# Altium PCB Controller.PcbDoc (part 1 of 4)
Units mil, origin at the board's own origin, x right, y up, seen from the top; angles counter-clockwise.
Board outline 5000 x 8750 mil, 6 copper layers (Top Layer, Layer 1, Layer 2, Layer 3, Layer 4, Bottom Layer), stack 92.6 mil thick; 303 components, 258 nets, 1062 pads, 274 vias.
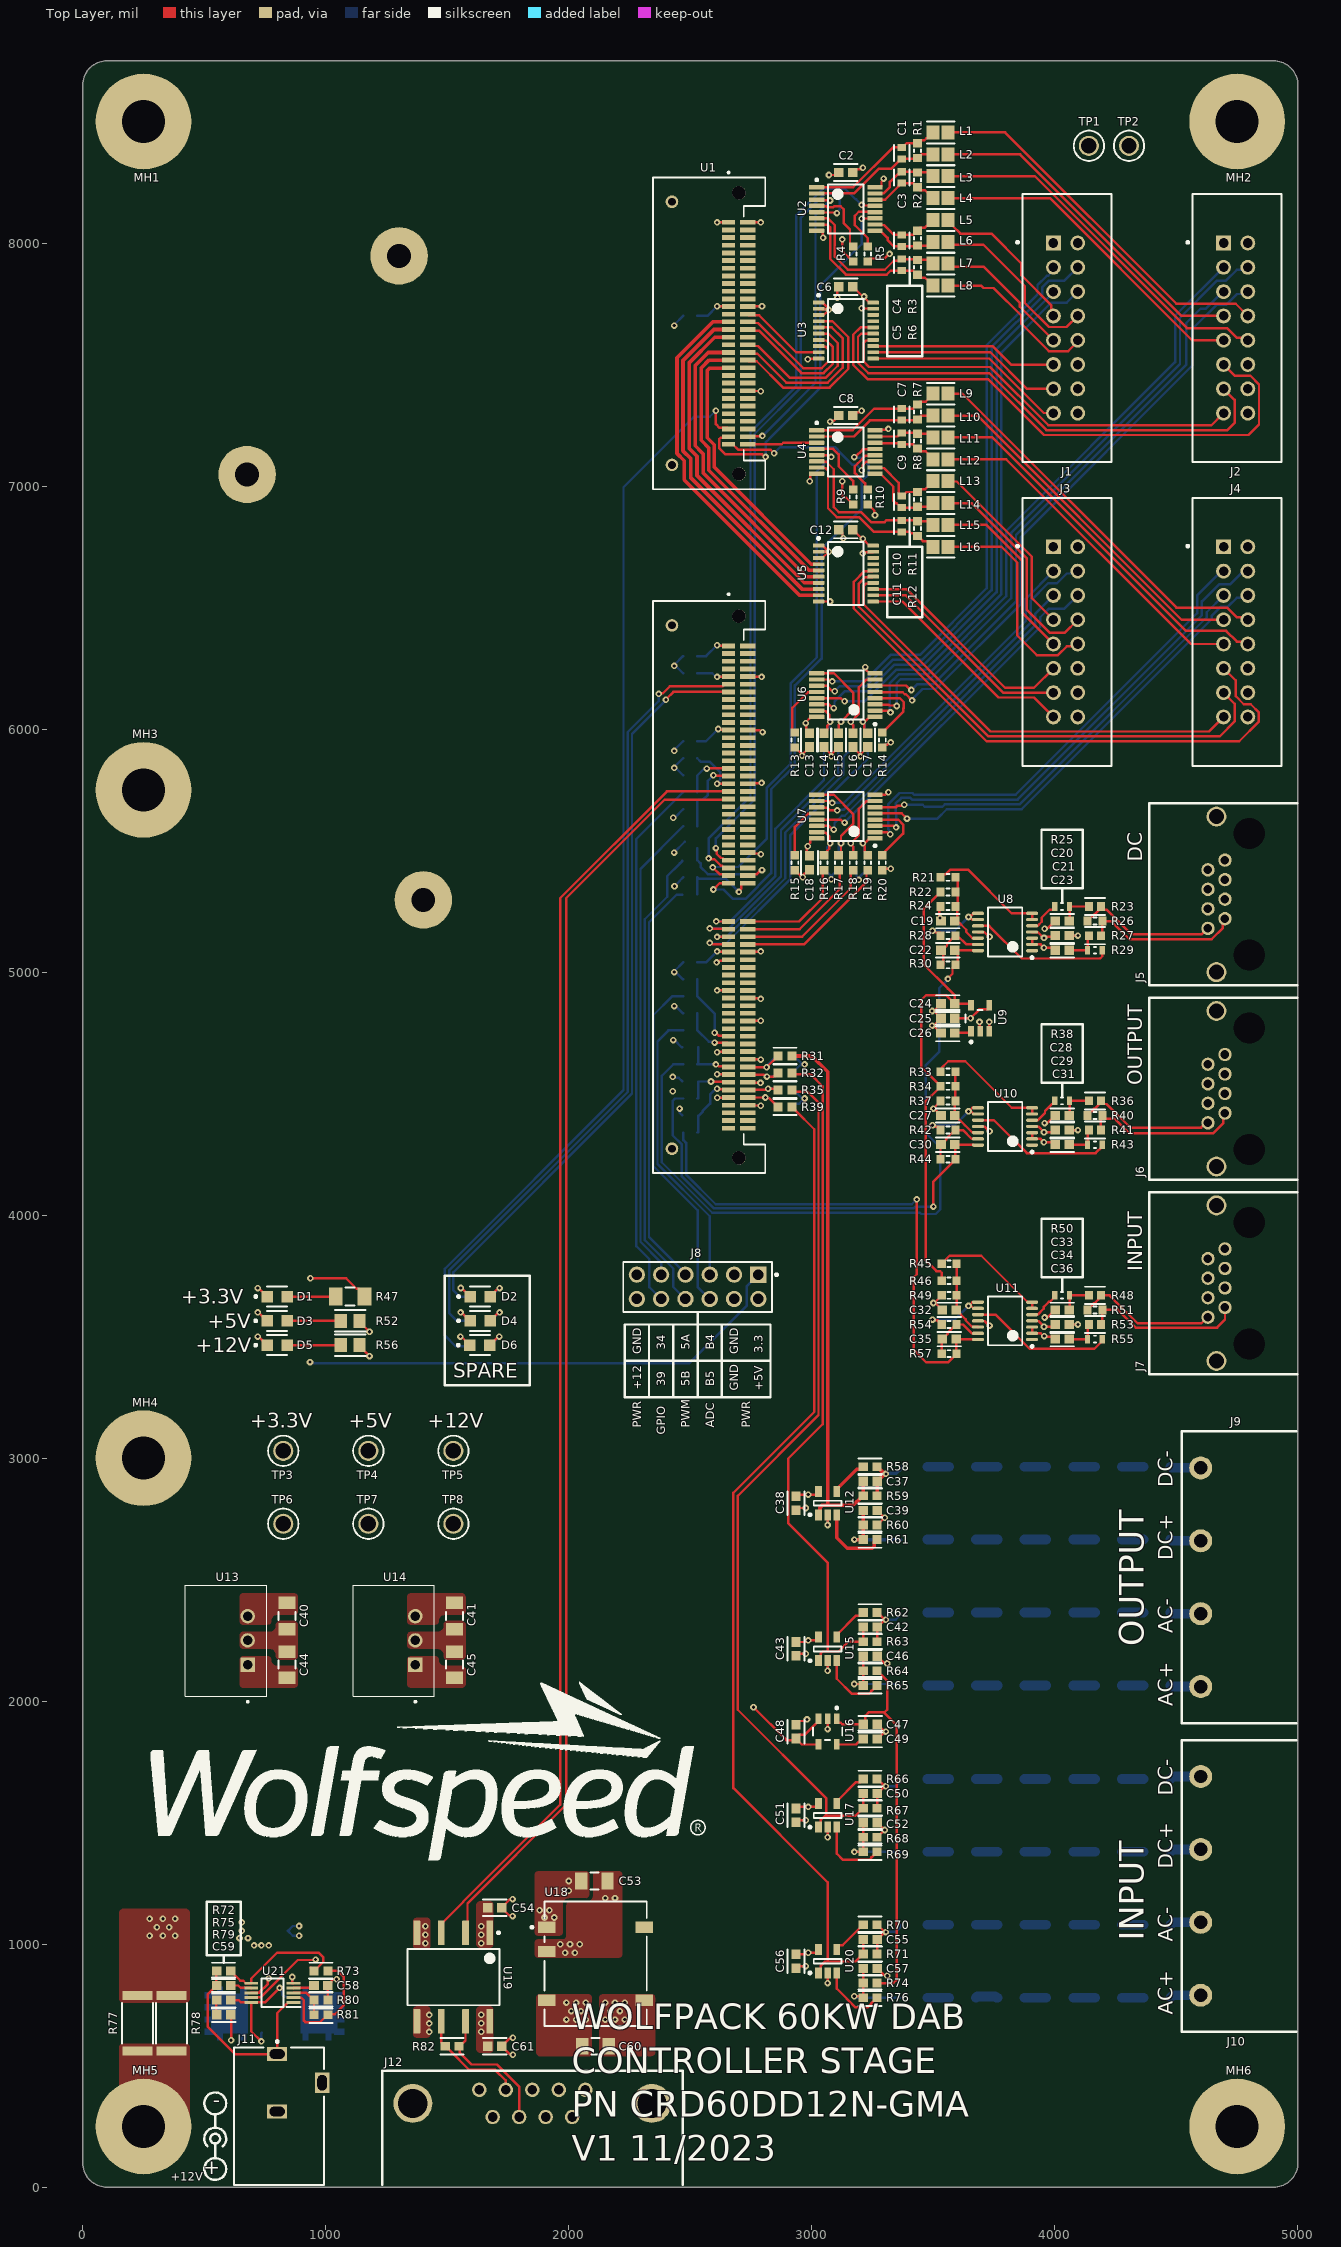
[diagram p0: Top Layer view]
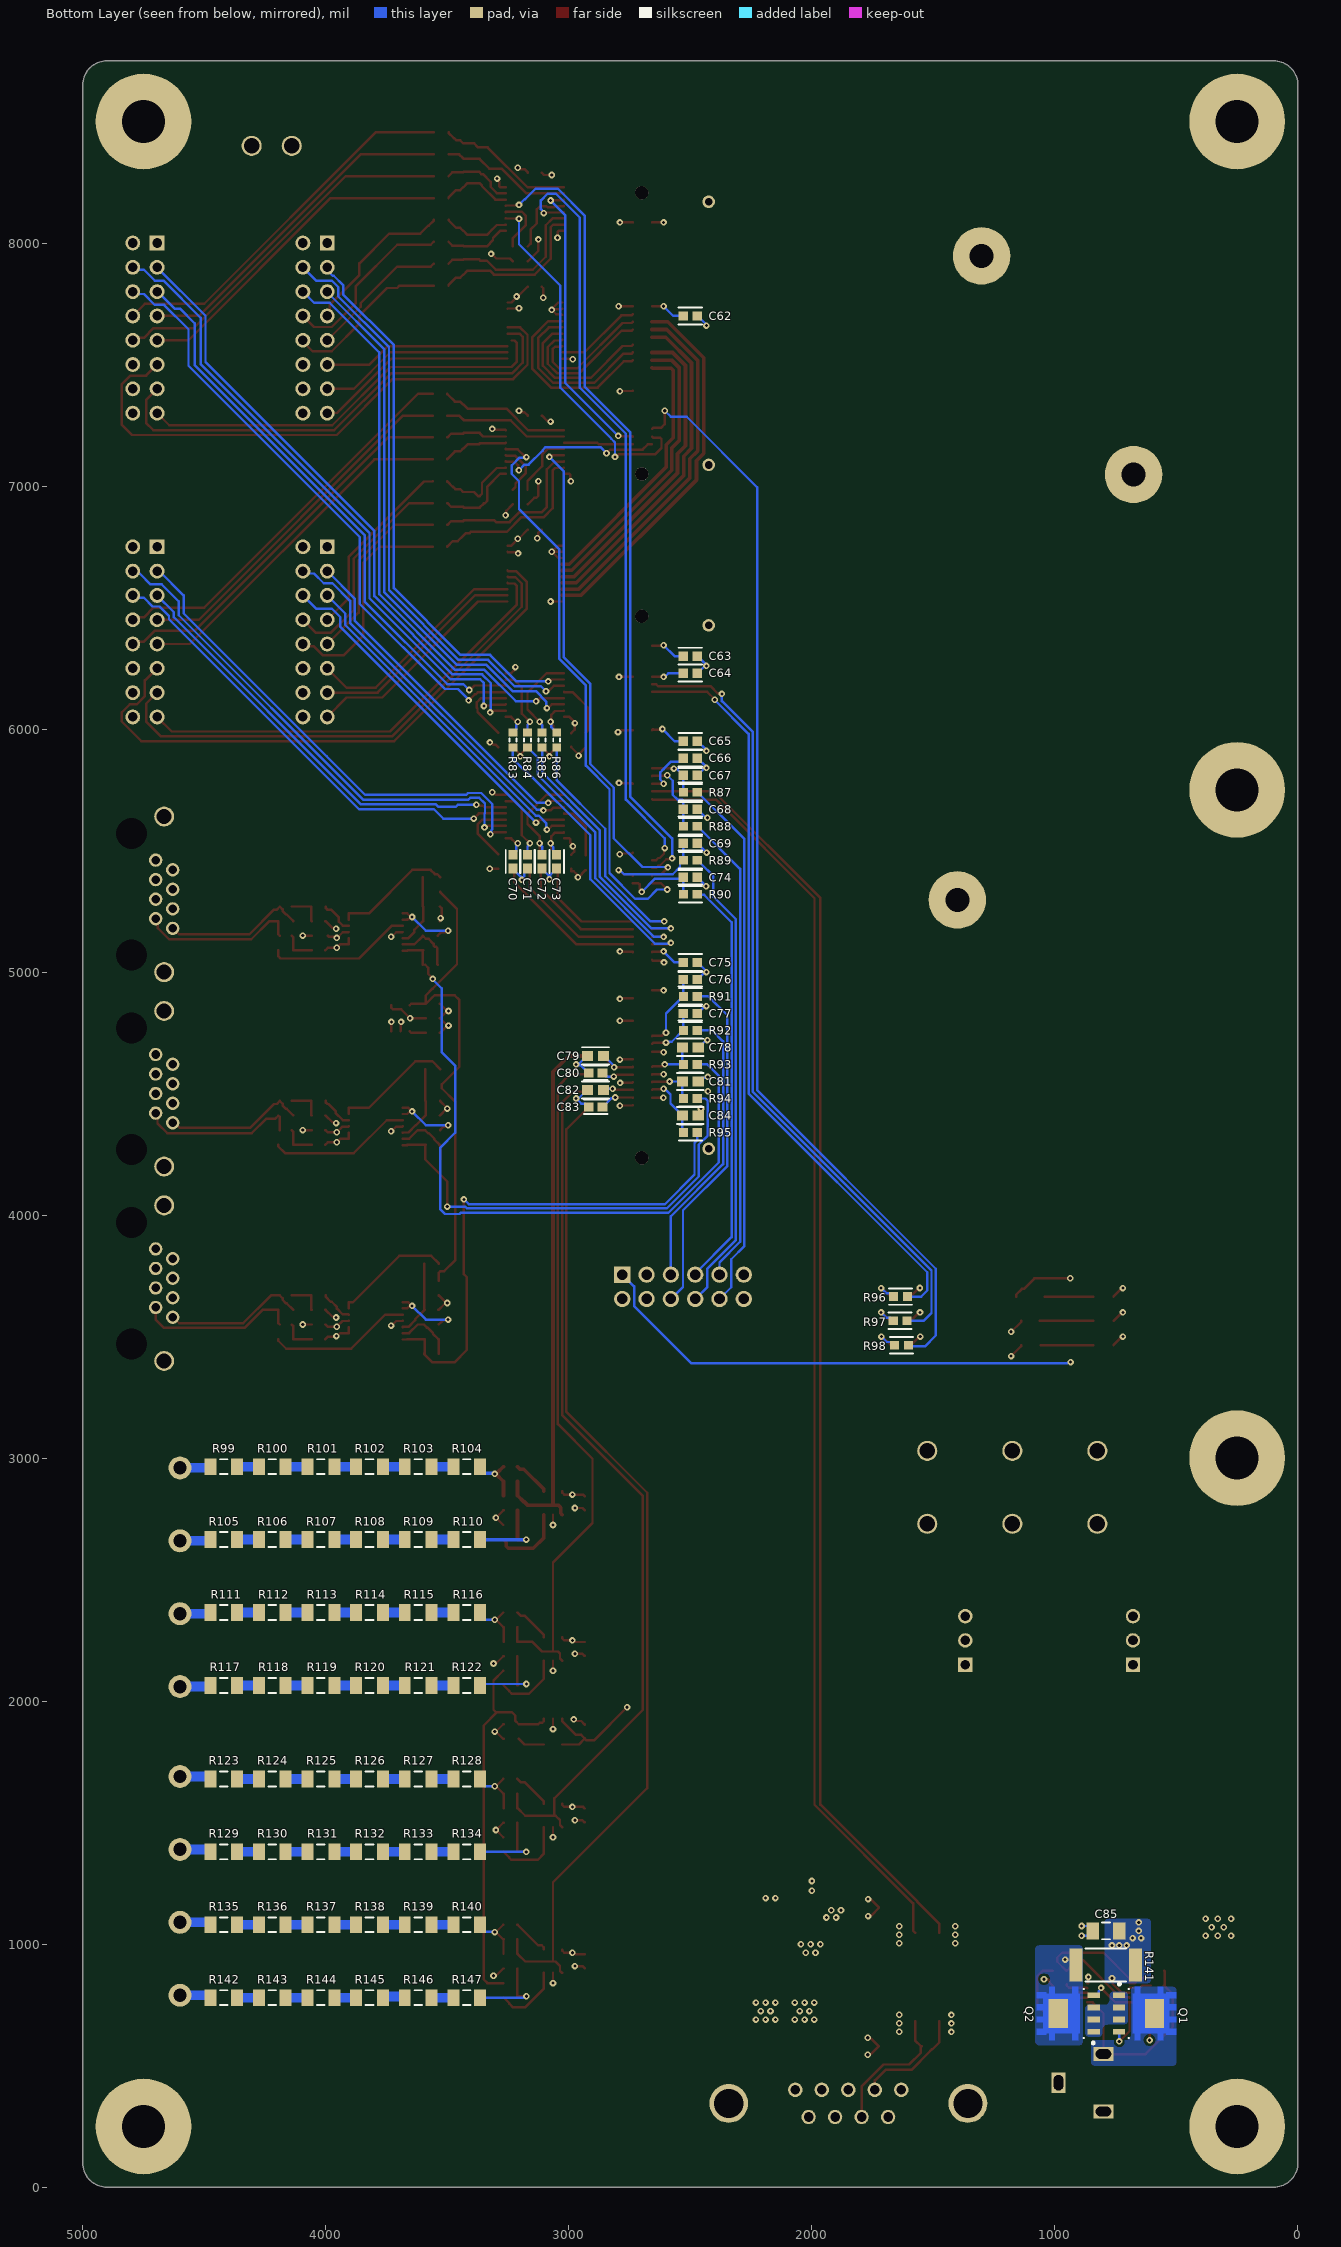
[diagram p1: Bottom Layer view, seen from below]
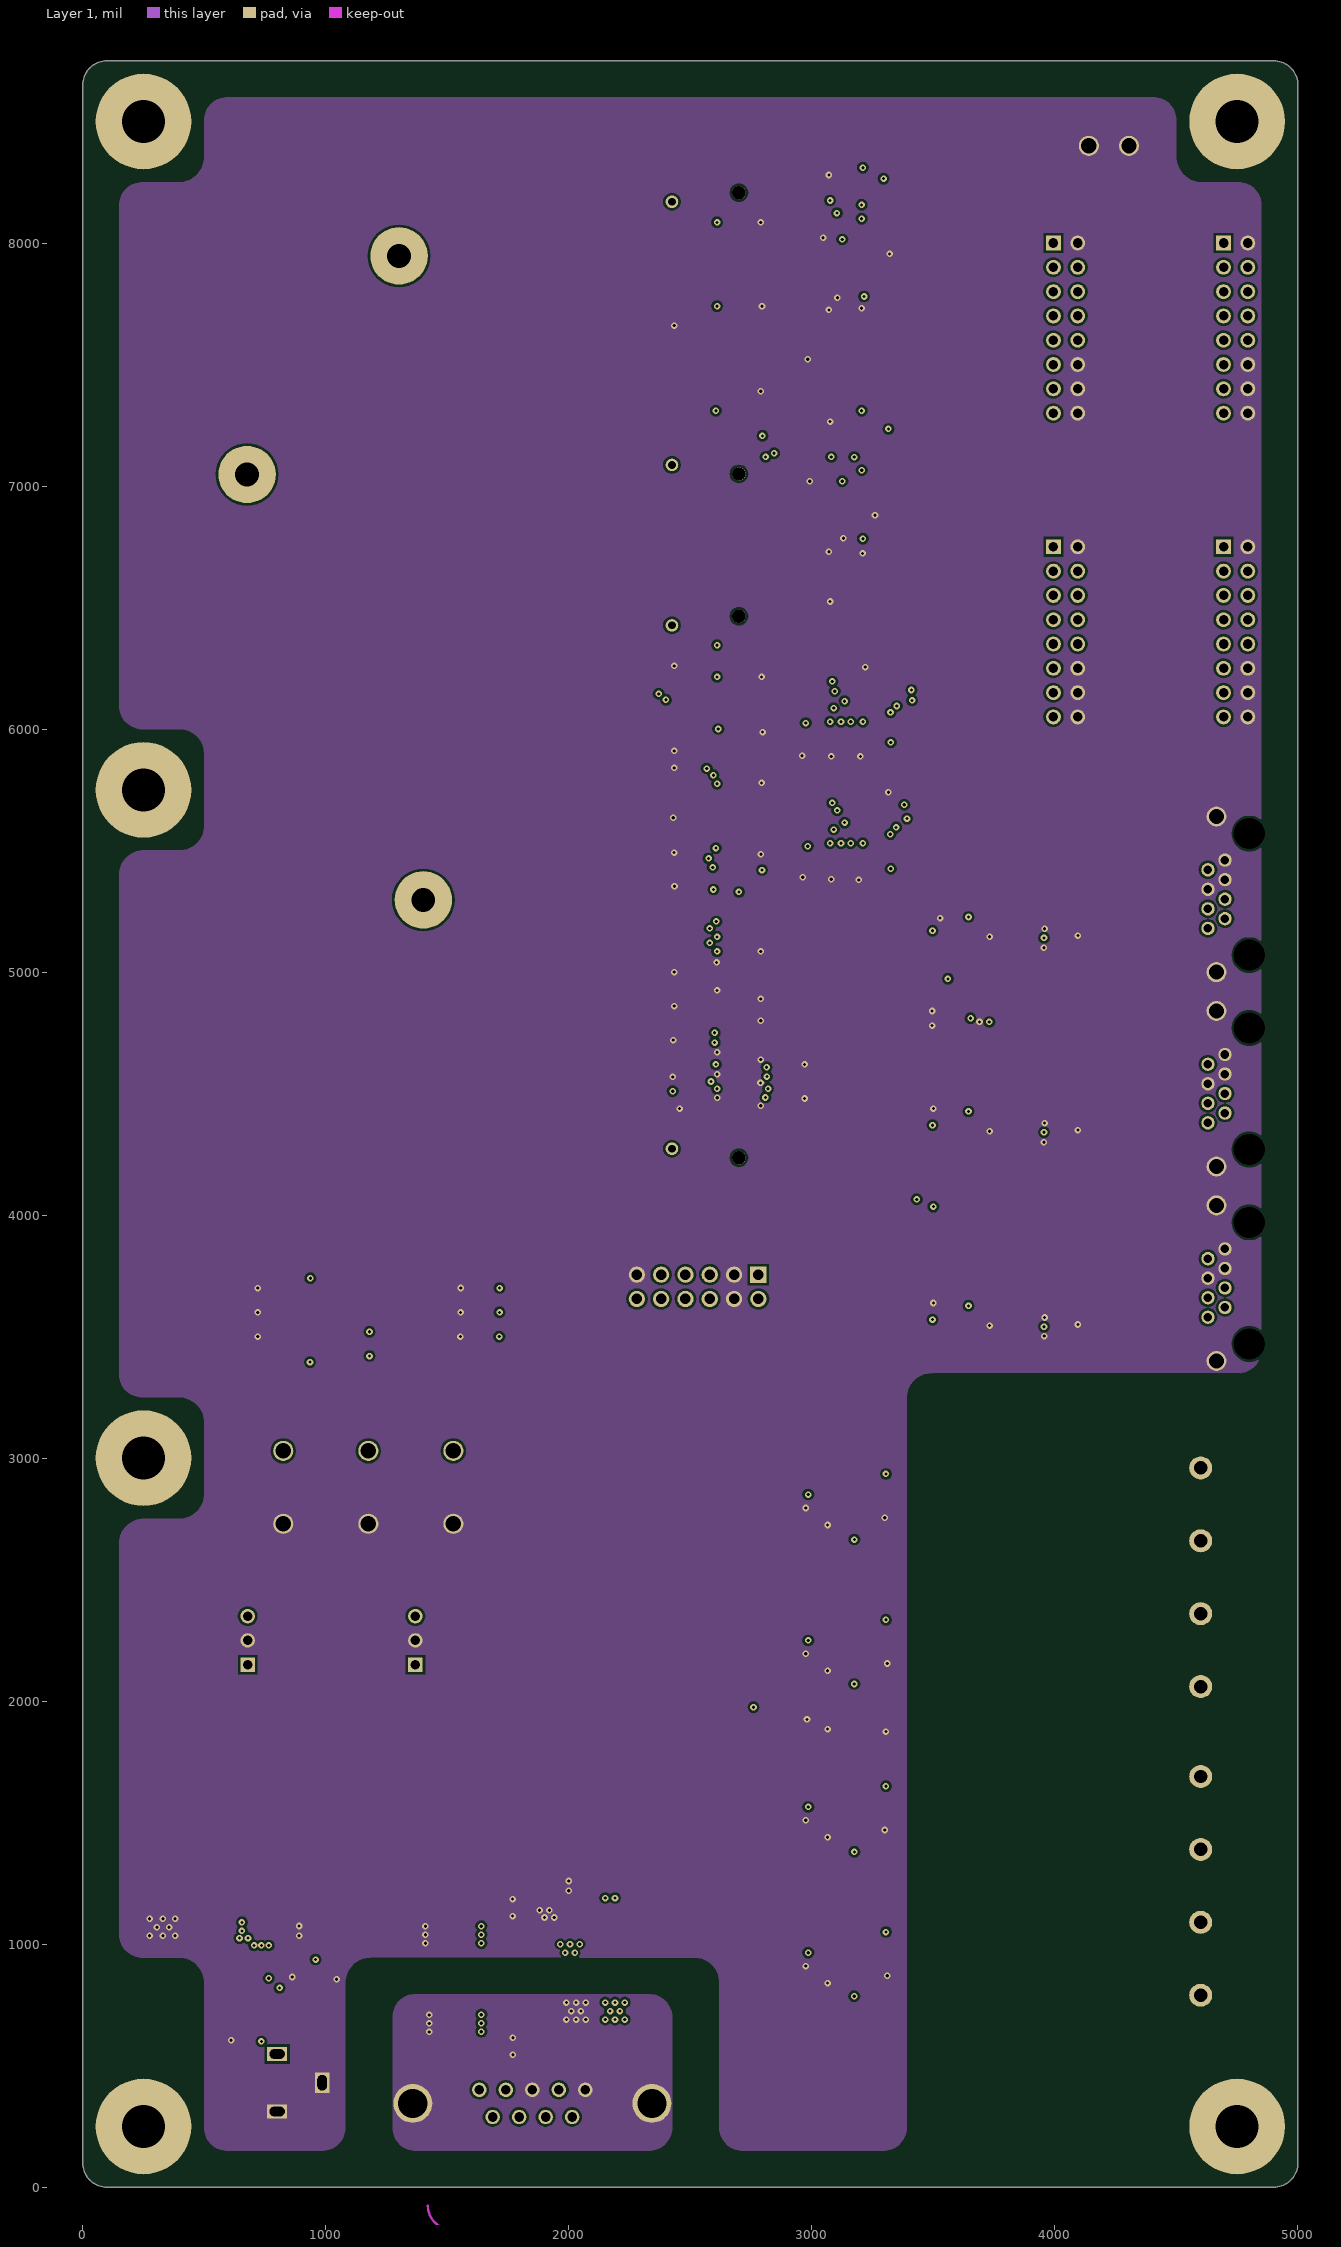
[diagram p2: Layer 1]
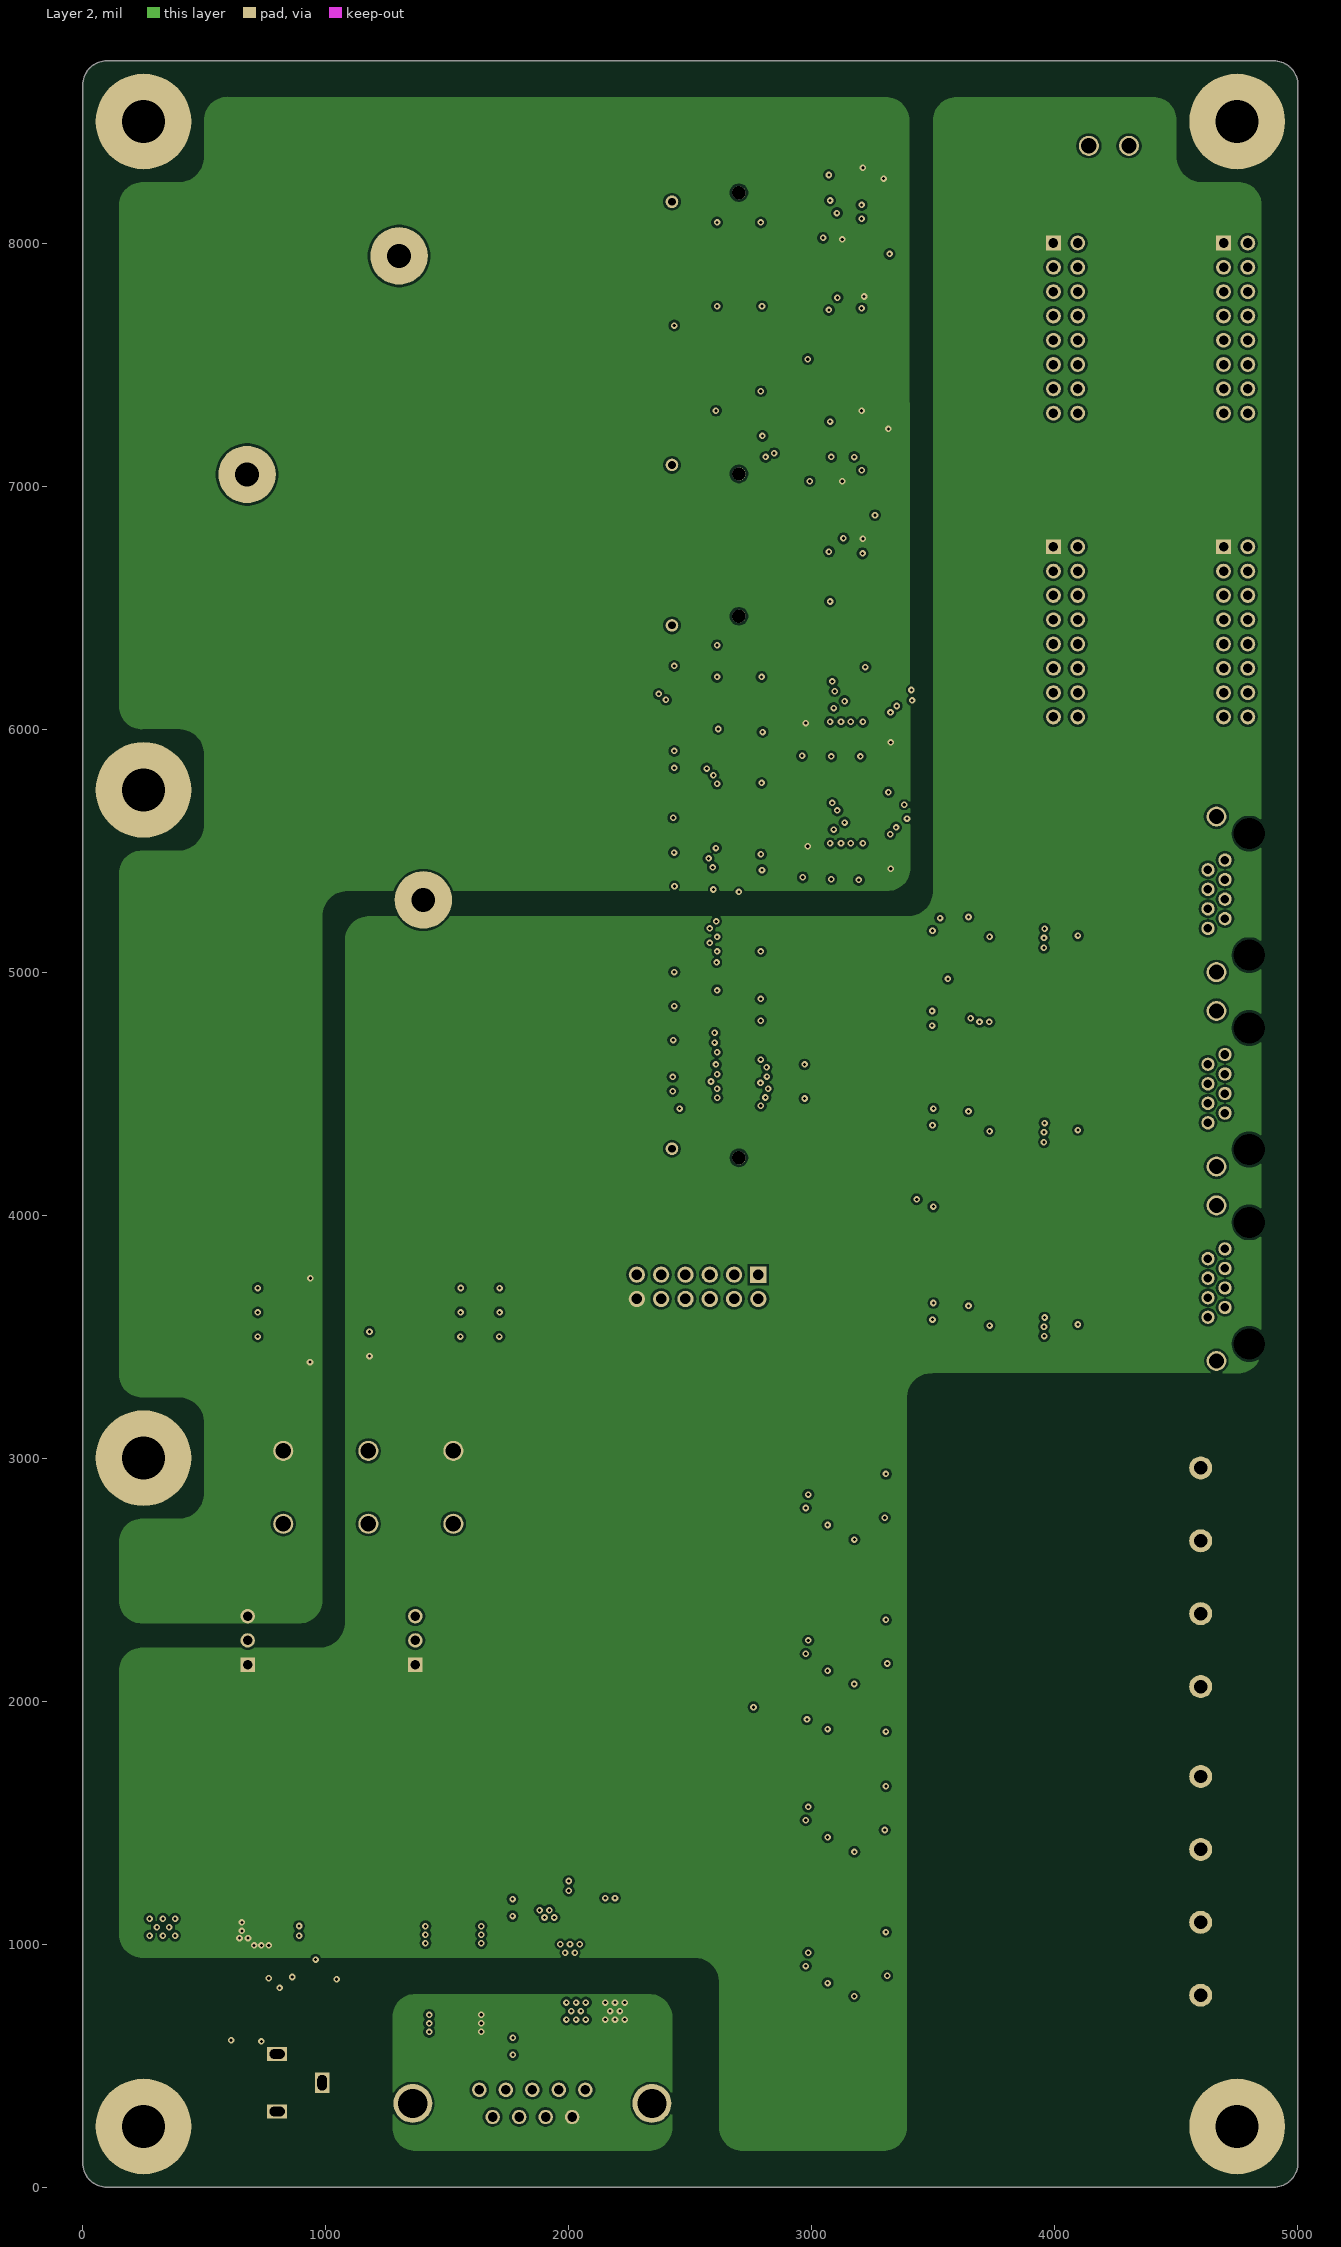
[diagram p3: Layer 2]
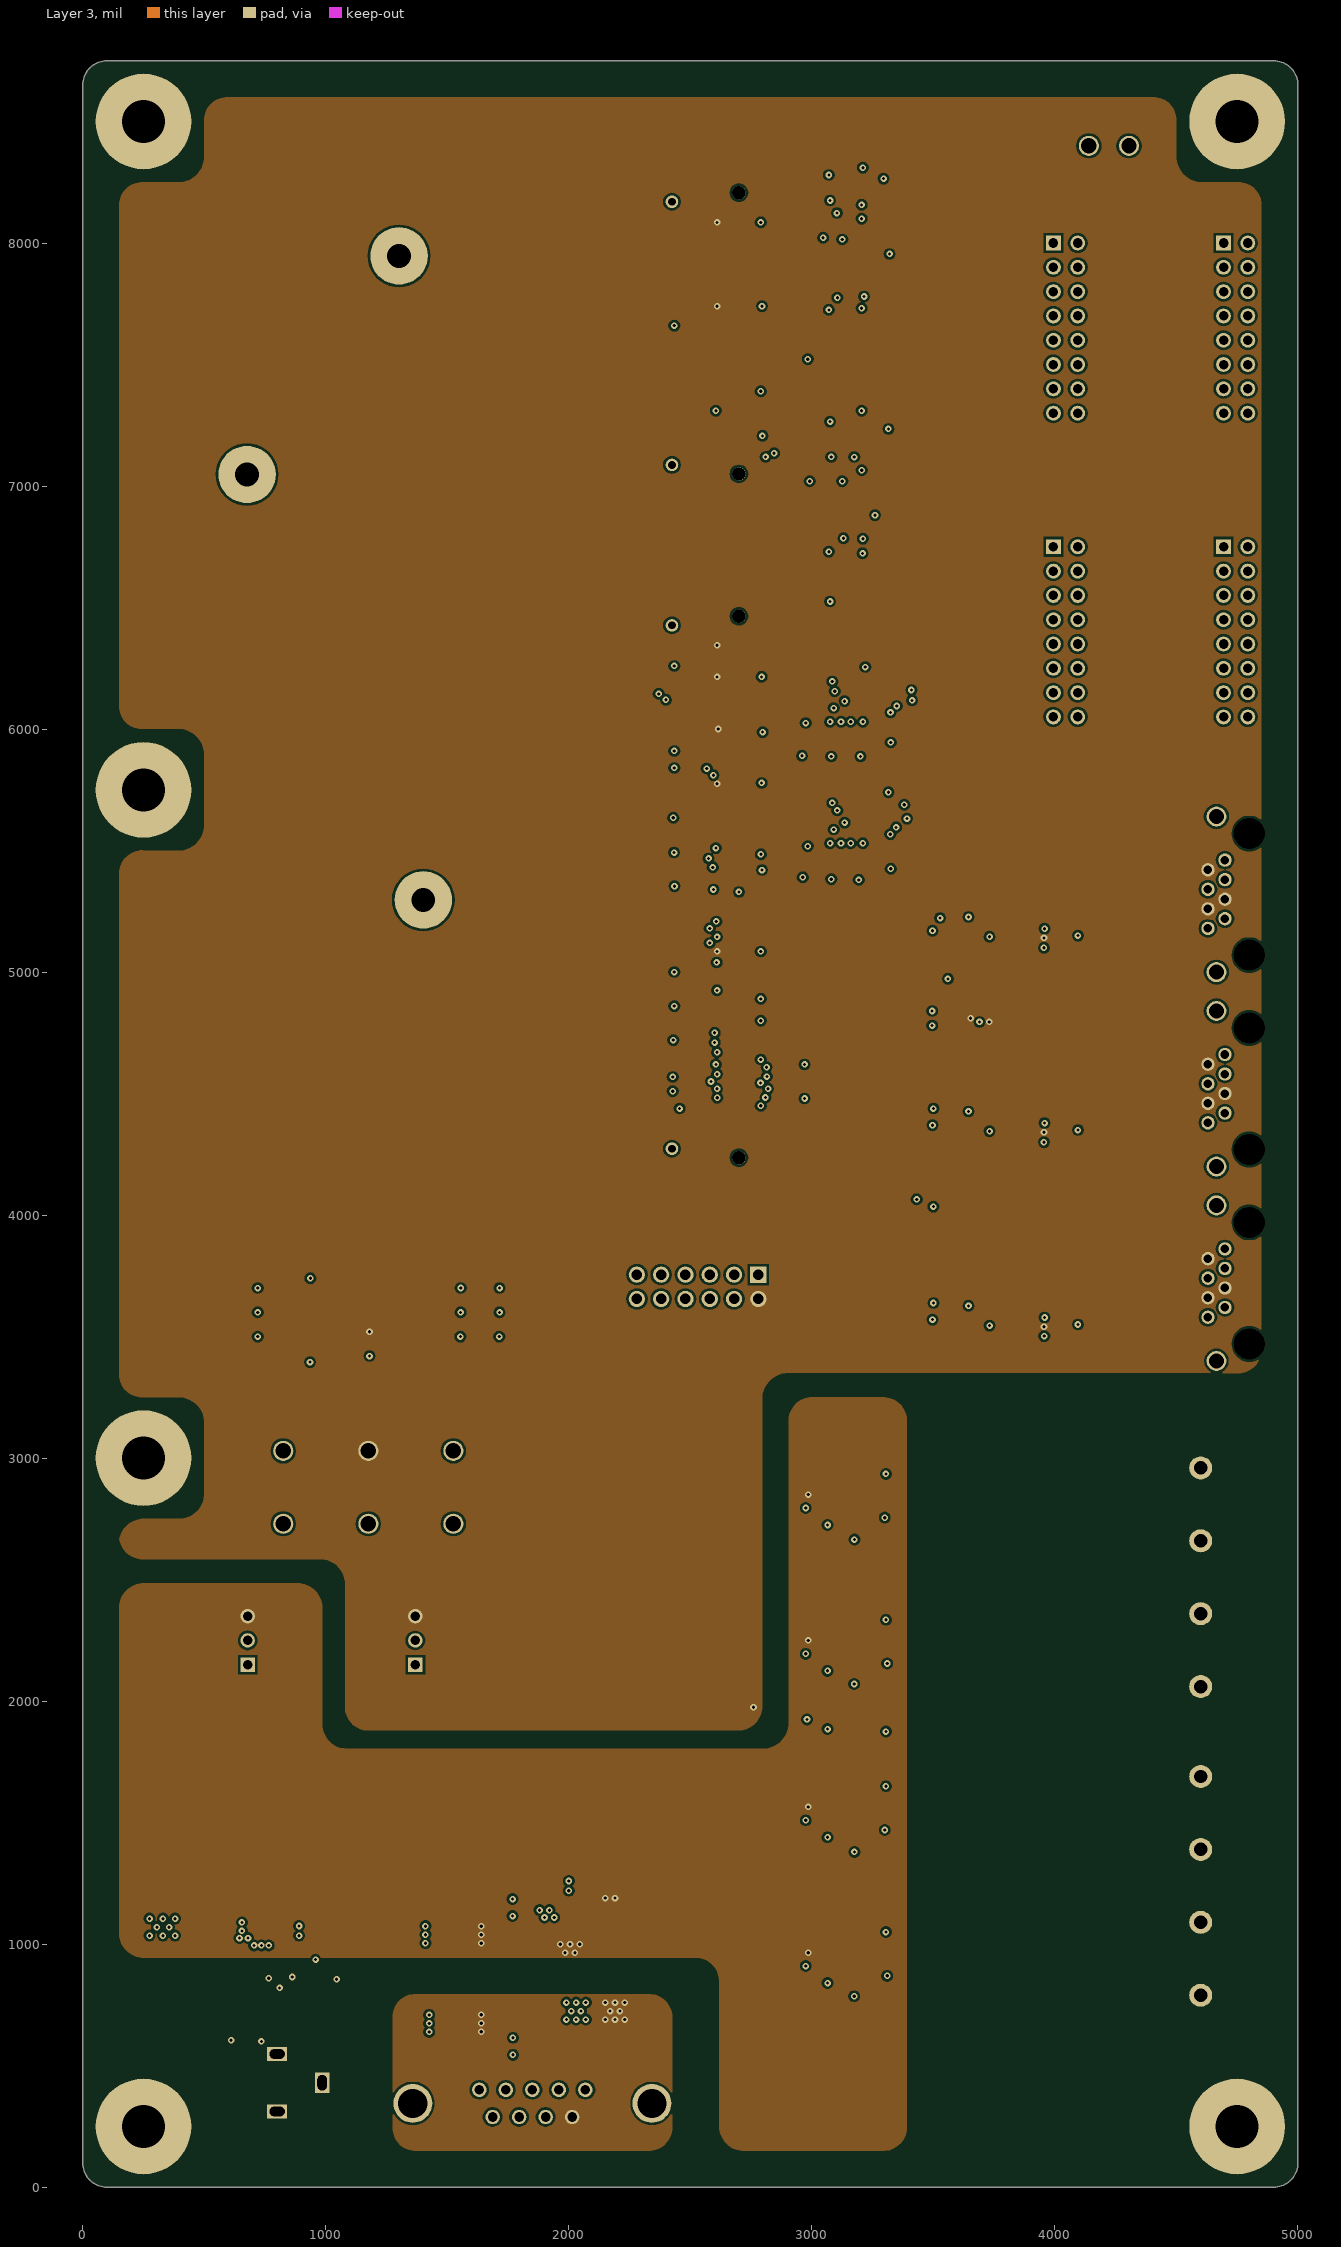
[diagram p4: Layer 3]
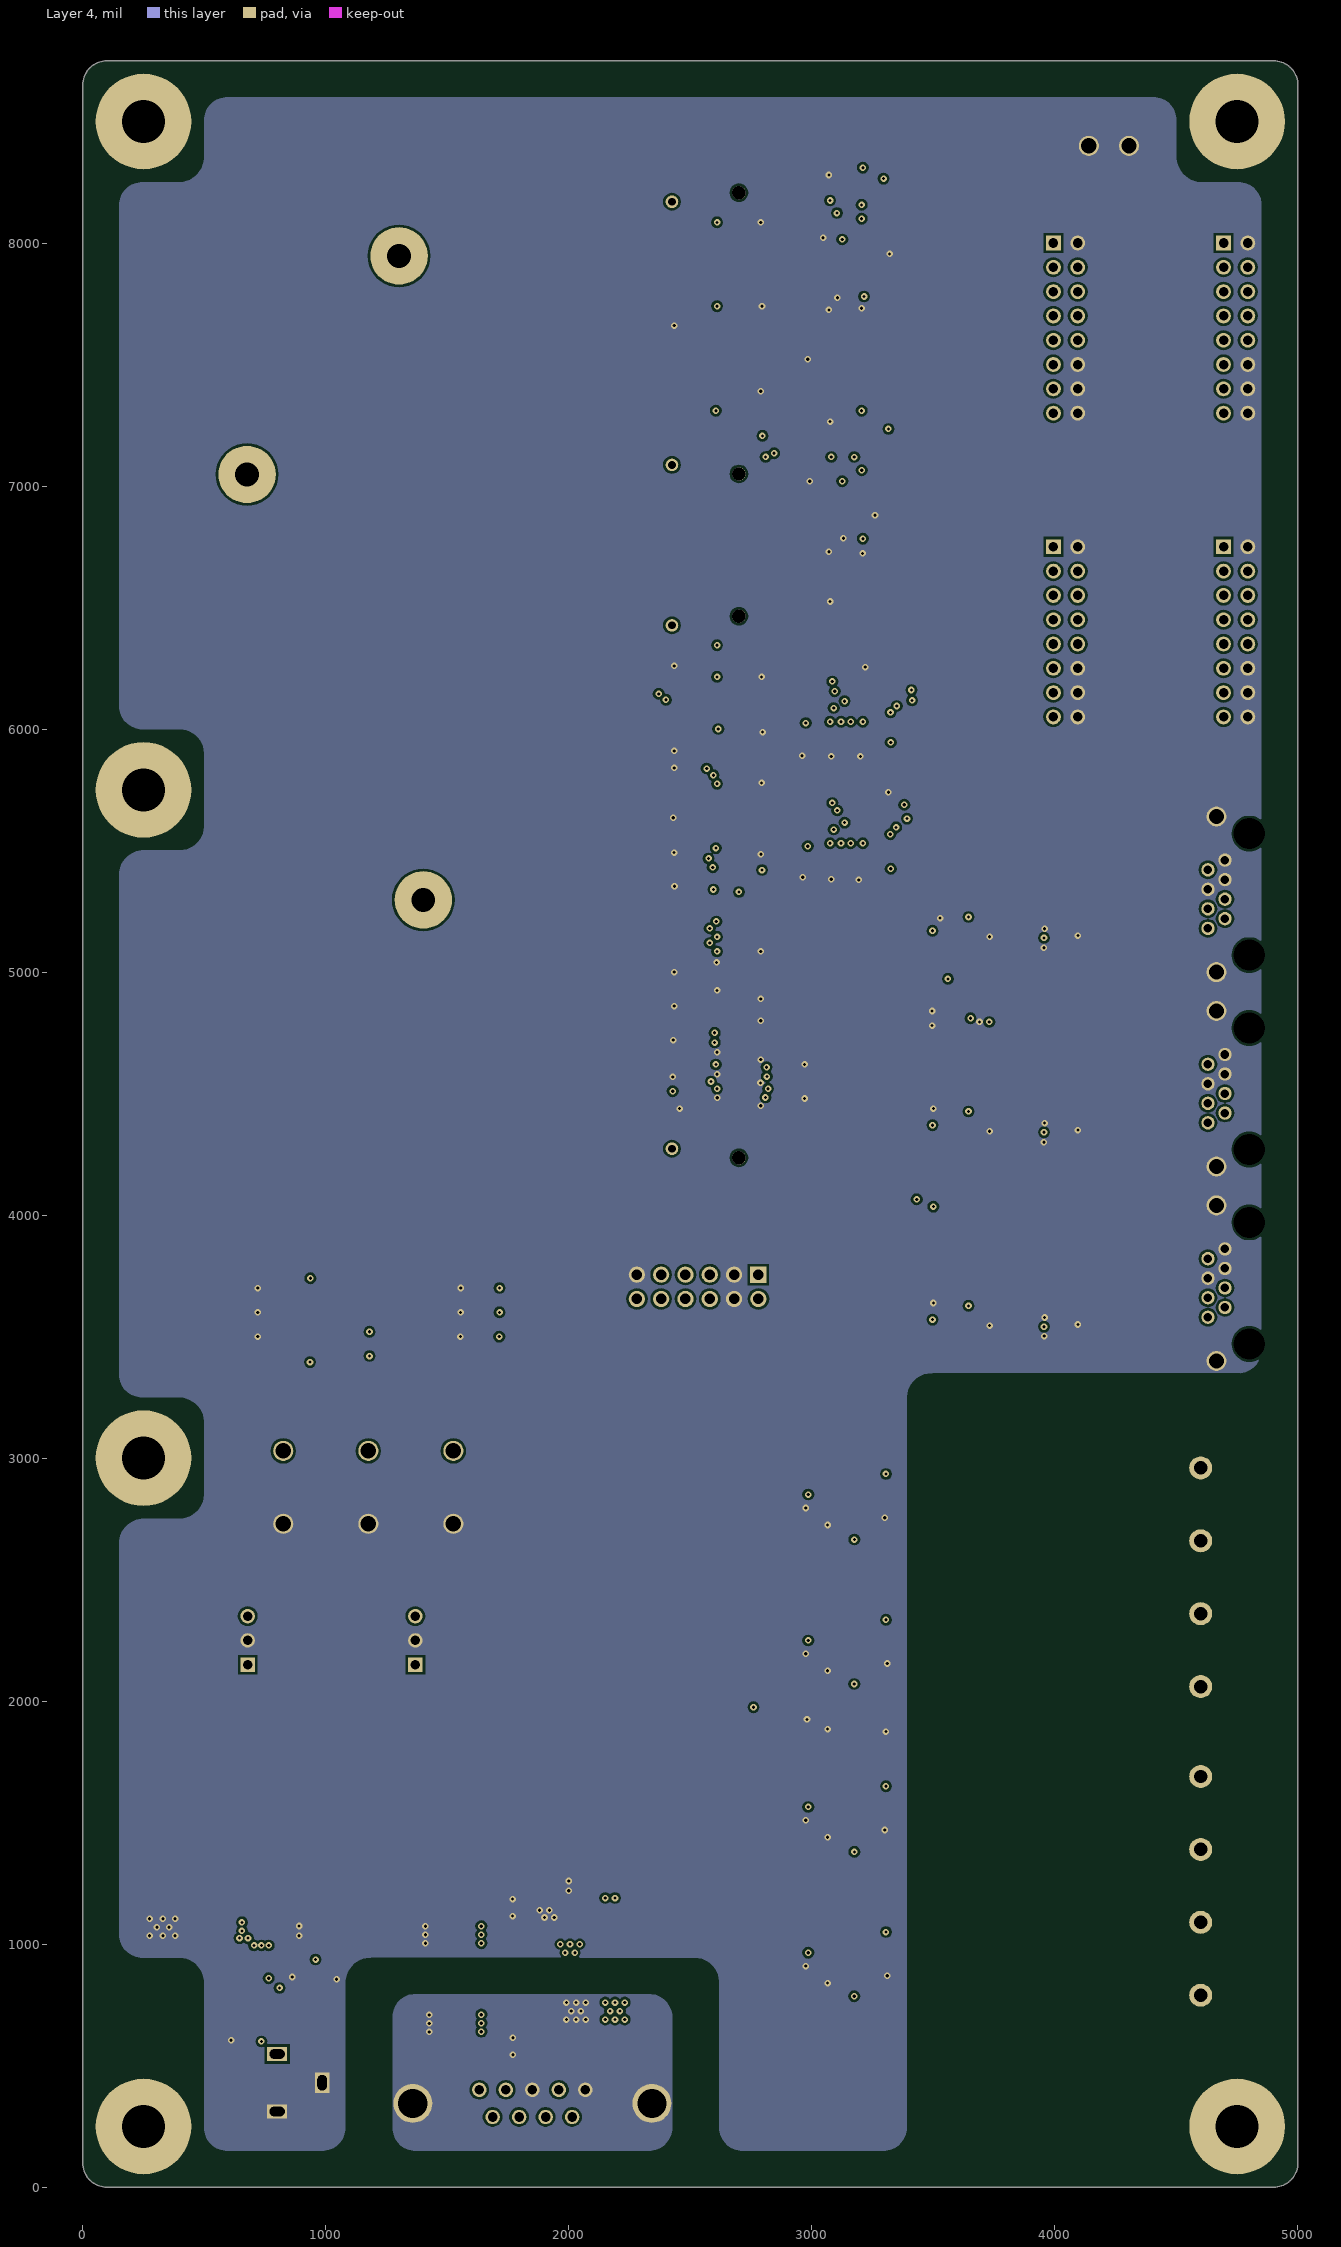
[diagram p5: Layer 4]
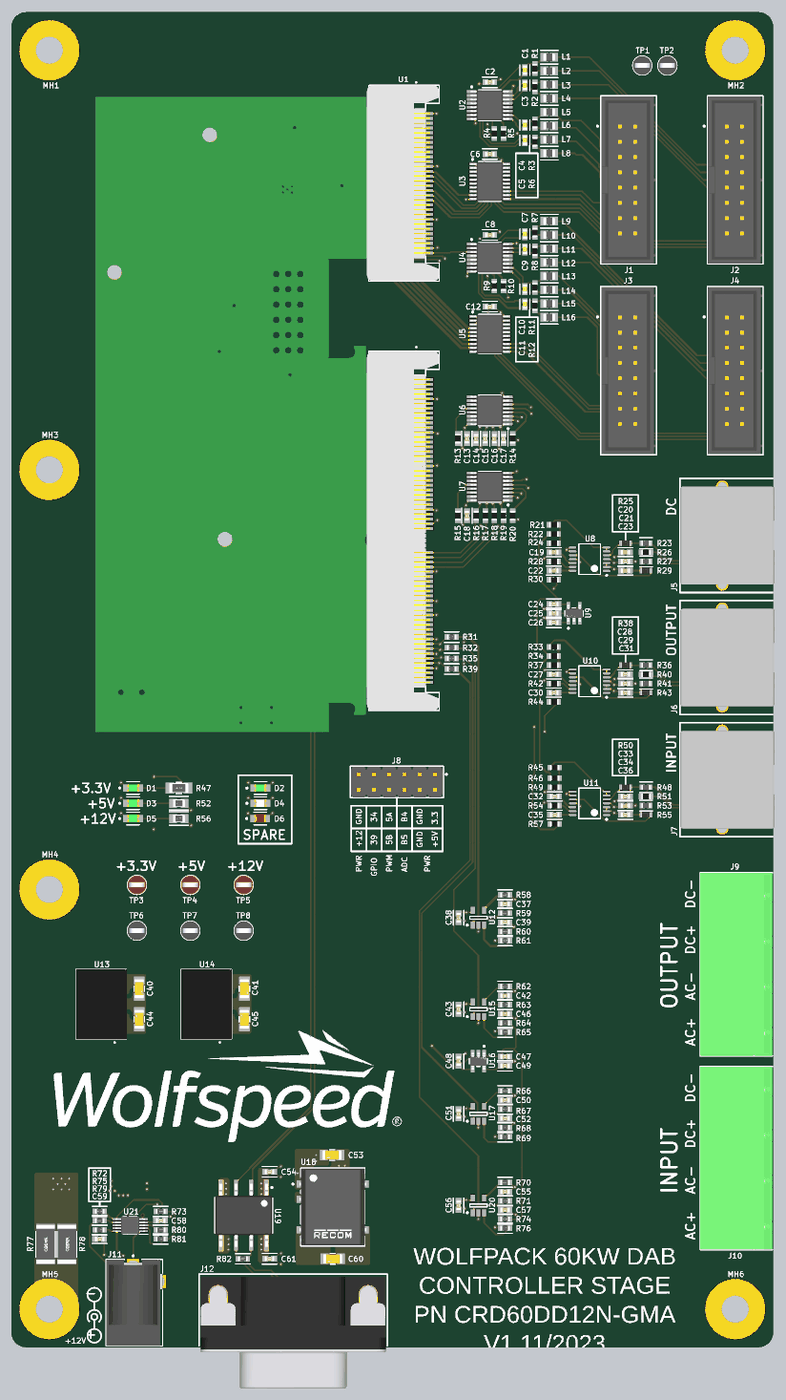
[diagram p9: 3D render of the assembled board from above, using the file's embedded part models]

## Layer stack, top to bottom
Top Solder: solder mask 0.4, Solder Resist, Dk 3.5
Top Layer: signal copper 1.4
Dielectric 2: prepreg 12.6, PP-006, Dk 4.1
Layer 1: signal copper 1.378
Dielectric 4: prepreg 12.6, PP-006, Dk 4.1
Layer 2: signal copper 1.378
Dielectric 1: dielectric 33.888, FR-4, Dk 4.8
Layer 3: signal copper 1.378
Dielectric 5: prepreg 12.6, PP-006, Dk 4.1
Layer 4: signal copper 1.378
Dielectric 3: prepreg 12.6, PP-006, Dk 4.1
Bottom Layer: signal copper 1.4
Bottom Solder: solder mask 0.4, Solder Resist, Dk 3.5

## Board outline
100,0 cw(c100,100) 0,100 0,8650 cw(c100,8650) 100,8750 4900,8750 cw(c4900,8650) 5000,8650 5000,100 cw(c4900,100) 4900,0

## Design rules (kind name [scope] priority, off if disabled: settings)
Clearance [All] p1: gap=10 ignorepadtopadclearanceinfootprint=FALSE except(0: Arc-Hole Track-Hole SMDPad-Hole THPad-Hole Via-Hole Fill-Hole Poly-Hole Region-Hole Text-Hole; 7.5: Arc-Arc Arc-Track Arc-SMDPad Track-Track Track-SMDPad SMDPad-SMDPad)
HoleSize [All] p1: absolutevalues=TRUE maxlimit=300 minlimit=6 maxpercent=80.000 minpercent=20.000
MinimumSolderMaskSliver [All] p1: minsoldermaskwidth=1.5
PlaneConnect [All] p1: planeconnectstyle=Direct reliefexpansion=20 reliefentries=4 reliefconductorwidth=10 reliefairgap=10
PolygonConnect [All] p1: connectstyle=Direct reliefconductorwidth=10 reliefentries=4 polygonreliefangle="90 Angle" airgapwidth=10
RoutingVias [All] p1: holewidth=28 width=50 viastyle="Through Hole" minholewidth=28 minwidth=50 maxholewidth=28 maxwidth=50
SilkToSilkClearance [All] p1: silktosilkclearance=2
SilkToSolderMaskClearance [IsPad] p1: minsilkscreentomaskgap=2 clearancetoexposedcopper=TRUE
SolderMaskExpansion [All] p1: expansion=4 istentingtop=FALSE
Width [All] p1: maxlimit=100 minlimit=10 preferedwidth=10
25 further rules are at their usual default settings.

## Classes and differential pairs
component class "Auxiliary Power": C24 C25 C26 C40 C41 C44 C45 C47 C48 C49 C53 C58 C59 C60 C67 C73 C74 C77 C82 D1 D2 D3 D4 D5 D6 J8 J11 MH1 MH2 MH3 MH4 MH5 MH6 MH7 Q1 Q2 R47 R52 R56 R72 R73 R75 R77 R78 R79 R80 R81 R87 R88 R89 R90 R91 R92 R96 R97 R98 R141 TP1 TP2 TP3 TP4 TP5 TP6 TP7 TP8 U9 U13 U14 U16 U18 U21
component class "Gate Drivers": C1 C2 C3 C4 C5 C6 C7 C8 C9 C10 C11 C12 C13 C14 C15 C16 C17 C18 C70 C71 C73 C78 J1 J2 J3 J4 L1 L2 L3 L4 L5 L6 L7 L8 L9 L10 L11 L12 L13 L14 L15 L16 R1 R2 R3 R4 R5 R6 R7 R8 R9 R10 R11 R12 R13 R14 R15 R16 R17 R18 R19 R20 R83 R84 R85 R86 U2 U3 U4 U5 U6 U7
component class "Current Sense": C19 C20 C21 C22 C23 C27 C28 C29 C30 C31 C32 C33 C34 C35 C36 C78 C81 C84 J5 J6 J7 R21 R22 R23 R24 R25 R26 R27 R28 R29 R30 R33 R34 R36 R37 R38 R40 R41 R42 R43 R44 R45 R46 R48 R49 R50 R51 R53 R54 R55 R57 R93 R94 R95 U8 U10 U11
component class "Voltage Sense": C37 C38 C39 C42 C43 C46 C50 C51 C52 C55 C56 C57 C67 C74 C81 C82 J9 J10 R31 R32 R35 R39 R58 R59 R60 R61 R62 R63 R64 R65 R66 R67 R68 R69 R70 R71 R74 R76 R99 R100 R101 R102 R103 R104 R105 R106 R107 R108 R109 R110 R111 R112 R113 R114 R115 R116 R117 R118 R119 R120 R121 R122 R123 R124 R125 R126 R127 R128 R129 R130 R131 R132 R133 R134 R135 R136 R137 R138 R139 R140 R142 R143 R144 R145 R146 R147 U12 U15 U17 U20
component class Controller: C54 C61 C67 C70 C71 C73 C74 C81 J12 R82 U1 U19

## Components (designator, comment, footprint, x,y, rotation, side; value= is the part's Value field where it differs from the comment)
C1 "CBR06C270FAGAC" FP-CBR06C-MFG 3370,8370 r90 top value=27pF (schematic designator C23)
C2 "C0603C104K3RACTU" FP-C0603C-CF-IPC_B 3140,8290 r180 top value=0.10μF (schematic designator C25)
C3 "CBR06C270FAGAC" FP-CBR06C-MFG 3370,8270 r90 top value=27pF (schematic designator C26)
C4 "CBR06C270FAGAC" FP-CBR06C-MFG 3370,8010 r270 top value=27pF (schematic designator C24)
C5 "CBR06C270FAGAC" FP-CBR06C-MFG 3370,7910 r270 top value=27pF (schematic designator C27)
C6 "C0603C104K3RACTU" FP-C0603C-CF-IPC_B 3140,7820 r180 top value=0.10μF (schematic designator C7)
C7 "CBR06C270FAGAC" FP-CBR06C-MFG 3370,7295 r90 top value=27pF (schematic designator C15)
C8 "C0603C104K3RACTU" FP-C0603C-CF-IPC_B 3140,7290 r180 top value=0.10μF (schematic designator C10)
C9 "CBR06C270FAGAC" FP-CBR06C-MFG 3370,7195 r90 top value=27pF (schematic designator C21)
C10 "CBR06C270FAGAC" FP-CBR06C-MFG 3370,6935 r270 top value=27pF (schematic designator C22)
C11 "CBR06C270FAGAC" FP-CBR06C-MFG 3370,6835 r270 top value=27pF (schematic designator C20)
C12 "C0603C104K3RACTU" FP-C0603C-CF-IPC_B 3140,6820 r180 top value=0.10μF (schematic designator C28)
C13 "C0603C104K3RACTU" FP-C0603C-CF-IPC_B 2990,5955 r270 top value=0.10μF (schematic designator C9)
C14 "CC0603KRX7R9BB101" FP-C0603C-CF-IPC_B 3050,5955 r270 top value=100pF (schematic designator C11)
C15 "CC0603KRX7R9BB101" FP-C0603C-CF-IPC_B 3110,5955 r270 top value=100pF (schematic designator C12)
C16 "CC0603KRX7R9BB101" FP-C0603C-CF-IPC_B 3170,5955 r270 top value=100pF (schematic designator C13)
C17 "CC0603KRX7R9BB101" FP-C0603C-CF-IPC_B 3230,5955 r270 top value=100pF (schematic designator C14)
C18 "C0603C104K3RACTU" FP-C0603C-CF-IPC_B 2990,5450 r270 top value=0.10μF (schematic designator C8)
C19 "CC0603KRX7R9BB101" FP-C0603C-CF-IPC_B 3560,5210 r180 top value=100pF (schematic designator C63)
C20 "CC0603KRX7R9BB101" FP-C0603C-CF-IPC_B 4030,5210 r180 top value=100pF (schematic designator C65)
C21 "C0603C104K3RACTU" FP-C0603C-CF-IPC_B 4030,5150 r0 top value=0.10μF (schematic designator C61)
C22 "CC0603KRX7R9BB101" FP-C0603C-CF-IPC_B 3560,5090 r0 top value=100pF (schematic designator C60)
C23 "CC0603KRX7R9BB101" FP-C0603C-CF-IPC_B 4030,5090 r180 top value=100pF (schematic designator C64)
C24 "C0603C104K3RACTU" FP-C0603C-CF-IPC_B 3560,4870 r180 top value=0.10μF (schematic designator C72)
C25 "C0603C104K3RACTU" FP-C0603C-CF-IPC_B 3560,4810 r180 top value=0.10μF (schematic designator C71)
C26 "C0603C104K3RACTU" FP-C0603C-CF-IPC_B 3560,4750 r180 top value=0.10μF (schematic designator C73)
C27 "CC0603KRX7R9BB101" FP-C0603C-CF-IPC_B 3560,4410 r180 top value=100pF (schematic designator C57)
C28 "CC0603KRX7R9BB101" FP-C0603C-CF-IPC_B 4030,4410 r180 top value=100pF (schematic designator C59)
C29 "C0603C104K3RACTU" FP-C0603C-CF-IPC_B 4030,4350 r0 top value=0.10μF (schematic designator C55)
C30 "CC0603KRX7R9BB101" FP-C0603C-CF-IPC_B 3560,4290 r0 top value=100pF (schematic designator C54)
C31 "CC0603KRX7R9BB101" FP-C0603C-CF-IPC_B 4030,4290 r180 top value=100pF (schematic designator C58)
C32 "CC0603KRX7R9BB101" FP-C0603C-CF-IPC_B 3565,3610 r180 top value=100pF (schematic designator C52)
C33 "CC0603KRX7R9BB101" FP-C0603C-CF-IPC_B 4030,3610 r180 top value=100pF (schematic designator C40)
C34 "C0603C104K3RACTU" FP-C0603C-CF-IPC_B 4030,3550 r0 top value=0.10μF (schematic designator C41)
C35 "CC0603KRX7R9BB101" FP-C0603C-CF-IPC_B 3565,3490 r0 top value=100pF (schematic designator C50)
C36 "CC0603KRX7R9BB101" FP-C0603C-CF-IPC_B 4030,3490 r180 top value=100pF (schematic designator C53)
C37 "C0603C472K3RAC7867" FP-C0603C-CF-IPC_B 3240,2905 r180 top value=4.7nF (schematic designator C29)
C38 "C0603C104K3RACTU" FP-C0603C-CF-IPC_B 2935,2815 r270 top value=0.10μF (schematic designator C30)
C39 "C0603C472K3RAC7867" FP-C0603C-CF-IPC_B 3240,2785 r0 top value=4.7nF (schematic designator C32)
C40 "CL31B106KAHSFNE" FP-CL31-IPC_B 840,2350 r270 top value=10μF (schematic designator C39)
C41 "CL31B106KAHSFNE" FP-CL31-IPC_B 1530,2350 r270 top value=10μF (schematic designator C37)
C42 "CC0603KRX7R9BB101" FP-C0603C-CF-IPC_B 3240,2305 r180 top value=100pF
C43 "C0603C104K3RACTU" FP-C0603C-CF-IPC_B 2935,2215 r270 top value=0.10μF (schematic designator C44)
C44 "CL31B106KAHSFNE" FP-CL31-IPC_B 840,2150 r90 top value=10μF (schematic designator C38)
C45 "CL31B106KAHSFNE" FP-CL31-IPC_B 1530,2150 r90 top value=10μF (schematic designator C36)
C46 "CC0603KRX7R9BB101" FP-C0603C-CF-IPC_B 3240,2185 r0 top value=100pF (schematic designator C48)
C47 "C0603C104K3RACTU" FP-C0603C-CF-IPC_B 3240,1905 r0 top value=0.10μF (schematic designator C70)
C48 "C0603C104K3RACTU" FP-C0603C-CF-IPC_B 2935,1875 r90 top value=0.10μF (schematic designator C68)
C49 "C0603C104K3RACTU" FP-C0603C-CF-IPC_B 3240,1845 r0 top value=0.10μF (schematic designator C69)
C50 "C0603C472K3RAC7867" FP-C0603C-CF-IPC_B 3240,1620 r180 top value=4.7nF (schematic designator C3)
C51 "C0603C104K3RACTU" FP-C0603C-CF-IPC_B 2935,1530 r270 top value=0.10μF (schematic designator C4)
C52 "C0603C472K3RAC7867" FP-C0603C-CF-IPC_B 3240,1500 r0 top value=4.7nF (schematic designator C6)
C53 "CL31B106KAHSFNE" FP-CL31-IPC_B 2105,1260 r180 top value=10μF (schematic designator C66)
C54 "C0603C104K3RACTU" FP-C0603C-CF-IPC_B 1695,1150 r0 top value=0.10μF (schematic designator C1)
C55 "CC0603KRX7R9BB101" FP-C0603C-CF-IPC_B 3240,1020 r180 top value=100pF (schematic designator C43)
C56 "C0603C104K3RACTU" FP-C0603C-CF-IPC_B 2935,930 r270 top value=0.10μF (schematic designator C45)
C57 "CC0603KRX7R9BB101" FP-C0603C-CF-IPC_B 3240,900 r0 top value=100pF (schematic designator C49)
C58 "CC0805KRX7R9BB223" FP-C0603C-CF-IPC_B 980,830 r0 top value=22nF (schematic designator C35)
C59 "C0603C472K3RAC7867" FP-C0603C-CF-IPC_B 580,710 r0 top value=4.7nF (schematic designator C34)
C60 "CL31B106KAHSFNE" FP-CL31-IPC_B 2110,580 r180 top value=10μF (schematic designator C67)
C61 "C0603C104K3RACTU" FP-C0603C-CF-IPC_B 1695,580 r0 top value=0.10μF (schematic designator C2)
C62 "C0603C104K3RACTU" FP-C0603C-CF-IPC_B 2500,7700 r180 bottom value=0.10μF (schematic designator C85)
C63 "C0603C104K3RACTU" FP-C0603C-CF-IPC_B 2500,6300 r180 bottom value=0.10μF (schematic designator C81)
C64 "C0603C104K3RACTU" FP-C0603C-CF-IPC_B 2500,6230 r180 bottom value=0.10μF (schematic designator C80)
C65 "C0603C104K3RACTU" FP-C0603C-CF-IPC_B 2500,5950 r180 bottom value=0.10μF (schematic designator C84)
C66 "C0603C104K3RACTU" FP-C0603C-CF-IPC_B 2500,5880 r180 bottom value=0.10μF (schematic designator C82)
C67 "CL10C560JB8NNNC" FP-C0603C-CF-IPC_B 2500,5810 r180 bottom value=56pF (schematic designator C79)
C68 "CL10C560JB8NNNC" FP-C0603C-CF-IPC_B 2500,5670 r180 bottom value=56pF (schematic designator C78)
C69 "CL10C560JB8NNNC" FP-C0603C-CF-IPC_B 2500,5530 r180 bottom value=56pF (schematic designator C77)
C70 "CC0603KRX7R9BB101" FP-C0603C-CF-IPC_B 3230,5455 r270 bottom value=100pF (schematic designator C19)
C71 "CC0603KRX7R9BB101" FP-C0603C-CF-IPC_B 3170,5455 r270 bottom value=100pF (schematic designator C18)
C72 "CC0603KRX7R9BB101" FP-C0603C-CF-IPC_B 3110,5455 r270 bottom value=100pF (schematic designator C17)
C73 "CC0603KRX7R9BB101" FP-C0603C-CF-IPC_B 3050,5455 r270 bottom value=100pF (schematic designator C16)
C74 "CL10C560JB8NNNC" FP-C0603C-CF-IPC_B 2500,5390 r180 bottom value=56pF (schematic designator C76)
C75 "C0603C104K3RACTU" FP-C0603C-CF-IPC_B 2500,5040 r180 bottom value=0.10μF (schematic designator C83)
C76 "CL10C560JB8NNNC" FP-C0603C-CF-IPC_B 2500,4970 r180 bottom value=56pF (schematic designator C75)
C77 "CL10C560JB8NNNC" FP-C0603C-CF-IPC_B 2500,4830 r180 bottom value=56pF (schematic designator C74)
C78 "GCM188R71C274KA37D" FP-GCM188-0_1-IPC_A 2500,4690 r180 bottom value=0.27μF (schematic designator C62)
C79 "GCM188R71C274KA37D" FP-GCM188-0_1-IPC_A 2890,4655 r0 bottom value=0.27μF (schematic designator C31)
C80 "GRM1885C1H102GA01D" FP-C0603C-CF-IPC_B 2890,4585 r0 bottom value=1nF (schematic designator C46)
C81 "GCM188R71C274KA37D" FP-GCM188-0_1-IPC_A 2500,4550 r180 bottom value=0.27μF (schematic designator C56)
C82 "GCM188R71C274KA37D" FP-GCM188-0_1-IPC_A 2890,4515 r0 bottom value=0.27μF (schematic designator C5)
C83 "GRM1885C1H102GA01D" FP-C0603C-CF-IPC_B 2890,4445 r0 bottom value=1nF (schematic designator C47)
C84 "GCM188R71C274KA37D" FP-GCM188-0_1-IPC_A 2500,4410 r180 bottom value=0.27μF (schematic designator C51)
C85 "CL31B106KAHSFNE" FP-CL31-IPC_B 790,1055 r0 bottom value=10μF (schematic designator C33)
D1 "LTST-C171GKT" FP-LTST-C171GKT-MFG 800,3665 r0 top value=GREEN
D2 "LTST-C171GKT" FP-LTST-C171GKT-MFG 1635,3665 r0 top value=GREEN (schematic designator D4)
D3 "LTST-C171GKT" FP-LTST-C171GKT-MFG 800,3565 r0 top value=GREEN (schematic designator D2)
D4 "LTST-C171KSKT" FP-LTST-C171GKT-MFG-YELLOW 1635,3565 r0 top value=YELLOW (schematic designator D5)
D5 "LTST-C171GKT" FP-LTST-C171GKT-MFG 800,3465 r0 top value=GREEN (schematic designator D3)
D6 "CMD17-21VRD/TR8" FP-LTST-C171GKT-MFG-RED 1633.66,3465 r0 top value=RED
J1 "SBH11-PBPC-D08-ST-BK" FP-SBH11-PBPC-D08-ST-BK-MFG 4050,7650 r270 top locked value=N/A (schematic designator J11)
J2 "SBH11-PBPC-D08-ST-BK" FP-SBH11-PBPC-D08-ST-BK-MFG 4750,7650 r270 top locked value=N/A (schematic designator J9)
J3 "SBH11-PBPC-D08-ST-BK" FP-SBH11-PBPC-D08-ST-BK-MFG 4050,6400 r270 top locked value=N/A (schematic designator J8)
J4 "SBH11-PBPC-D08-ST-BK" FP-SBH11-PBPC-D08-ST-BK-MFG 4750,6400 r270 top locked value=N/A (schematic designator J3)
J5 "2-406541-2" 2-406541-2 4800,5320 r90 top locked value=N/A (schematic designator J7)
J6 "2-406541-2" 2-406541-2 4800,4520 r90 top locked value=N/A (schematic designator J4)
J7 "2-406541-2" 2-406541-2 4800,3720 r90 top locked value=N/A (schematic designator J6)
J8 "61301221121" FP-61301221121-MFG 2530,3705 r180 top value=N/A (schematic designator J12)
J9 "1728879" 1728879 4600,2510 r90 top locked value=N/A (schematic designator J1)
J10 "1728879" 1728879 4600,1240 r90 top locked value=N/A (schematic designator J2)
J11 "PJ-102AH" CUI-PJ-102B_V 800,430 r270 top value=N/A (schematic designator J5)
J12 "L717SDE09PA4CH4RC309" L717SDE09PA4CH4RC309 1850,345 r0 top value=N/A (schematic designator J10)
L1 "MLZ2012N1R0LT000" FP-MLZ2012-0_85-IPC_B 3530,8455 r180 top value=1μH (schematic designator L11)
L2 "MLZ2012N1R0LT000" FP-MLZ2012-0_85-IPC_B 3530,8365 r180 top value=1μH (schematic designator L9)
L3 "MLZ2012N1R0LT000" FP-MLZ2012-0_85-IPC_B 3530,8275 r180 top value=1μH (schematic designator L15)
L4 "MLZ2012N1R0LT000" FP-MLZ2012-0_85-IPC_B 3530,8185 r180 top value=1μH (schematic designator L13)
L5 "MLZ2012N1R0LT000" FP-MLZ2012-0_85-IPC_B 3530,8095 r180 top value=1μH (schematic designator L10)
L6 "MLZ2012N1R0LT000" FP-MLZ2012-0_85-IPC_B 3530,8005 r180 top value=1μH (schematic designator L12)
L7 "MLZ2012N1R0LT000" FP-MLZ2012-0_85-IPC_B 3530,7915 r180 top value=1μH (schematic designator L14)
L8 "MLZ2012N1R0LT000" FP-MLZ2012-0_85-IPC_B 3530,7825 r180 top value=1μH (schematic designator L16)
L9 "MLZ2012N1R0LT000" FP-MLZ2012-0_85-IPC_B 3530,7380 r180 top value=1μH (schematic designator L3)
L10 "MLZ2012N1R0LT000" FP-MLZ2012-0_85-IPC_B 3530,7290 r180 top value=1μH (schematic designator L1)
L11 "MLZ2012N1R0LT000" FP-MLZ2012-0_85-IPC_B 3530,7200 r180 top value=1μH (schematic designator L7)
L12 "MLZ2012N1R0LT000" FP-MLZ2012-0_85-IPC_B 3530,7110 r180 top value=1μH (schematic designator L5)
L13 "MLZ2012N1R0LT000" FP-MLZ2012-0_85-IPC_B 3530,7020 r180 top value=1μH (schematic designator L6)
L14 "MLZ2012N1R0LT000" FP-MLZ2012-0_85-IPC_B 3530,6930 r180 top value=1μH (schematic designator L8)
L15 "MLZ2012N1R0LT000" FP-MLZ2012-0_85-IPC_B 3530,6840 r180 top value=1μH (schematic designator L2)
L16 "MLZ2012N1R0LT000" FP-MLZ2012-0_85-IPC_B 3530,6750 r180 top value=1μH (schematic designator L4)
MH1 "MH_M4_P" MH_M4_P 250,8500 r0 top (schematic designator MH7)
MH2 "MH_M4_P" MH_M4_P 4750,8500 r0 top
MH3 "MH_M4_P" MH_M4_P 250,5750 r0 top
MH4 "MH_M4_P" MH_M4_P 250,3000 r0 top
MH5 "MH_M4_P" MH_M4_P 250,250 r0 top (schematic designator MH1)
MH6 "MH_M4_P" MH_M4_P 4750,250 r0 top
Q1 "DMT12H007LPS-13" FP-PowerDI5060-8-MFG 631.34,715 r270 bottom value=N/A
Q2 "DMT12H007LPS-13" FP-PowerDI5060-8-MFG 945,715 r90 bottom value=N/A
R1 "RMCF0603FT100R" FP-AC0603-IPC_B 3435,8380 r270 top value=100Ω (schematic designator R41)
R2 "RMCF0603FT100R" FP-AC0603-IPC_B 3435,8260 r270 top value=100Ω (schematic designator R43)
R3 "RMCF0603FT100R" FP-AC0603-IPC_B 3435,8020 r90 top value=100Ω (schematic designator R42)
R4 "RT0603BRE0715KL" FP-AC0603-IPC_B 3170,7955 r270 top value=15kΩ (schematic designator R31)
R5 "RT0603BRE0715KL" FP-AC0603-IPC_B 3230,7955 r90 top value=15kΩ (schematic designator R36)
R6 "RMCF0603FT100R" FP-AC0603-IPC_B 3435,7900 r90 top value=100Ω (schematic designator R44)
R7 "RMCF0603FT100R" FP-AC0603-IPC_B 3435,7305 r270 top value=100Ω (schematic designator R37)
R8 "RMCF0603FT100R" FP-AC0603-IPC_B 3435,7185 r270 top value=100Ω (schematic designator R39)
R9 "RT0603BRE0715KL" FP-AC0603-IPC_B 3170,6955 r270 top value=15kΩ (schematic designator R21)
R10 "RT0603BRE0715KL" FP-AC0603-IPC_B 3230,6955 r90 top value=15kΩ (schematic designator R23)
R11 "RMCF0603FT100R" FP-AC0603-IPC_B 3435,6945 r90 top value=100Ω (schematic designator R40)
R12 "RMCF0603FT100R" FP-AC0603-IPC_B 3435,6825 r90 top value=100Ω (schematic designator R38)
R13 "RT0603BRE0715KL" FP-AC0603-IPC_B 2930,5955 r90 top value=15kΩ (schematic designator R30)
R14 "RT0603BRE0715KL" FP-AC0603-IPC_B 3290,5955 r270 top value=15kΩ (schematic designator R25)
R15 "RT0603BRE0715KL" FP-AC0603-IPC_B 2930,5450 r90 top value=15kΩ (schematic designator R24)
R16 "RC0603FR-07120RL" FP-AC0603-IPC_B 3050,5450 r90 top value=120Ω (schematic designator R35)
R17 "RC0603FR-07120RL" FP-AC0603-IPC_B 3110,5450 r90 top value=120Ω (schematic designator R34)
R18 "RC0603FR-07120RL" FP-AC0603-IPC_B 3170,5450 r90 top value=120Ω (schematic designator R33)
R19 "RC0603FR-07120RL" FP-AC0603-IPC_B 3230,5450 r90 top value=120Ω (schematic designator R32)
R20 "RT0603BRE0715KL" FP-AC0603-IPC_B 3290,5450 r270 top value=15kΩ (schematic designator R22)
R21 "RR0816P-273-D" FP-AC0603-IPC_B 3560,5390 r0 top value=27kΩ (schematic designator R134)
R22 "RMCF0603FT20K0" FP-AC0603-IPC_B 3560,5330 r180 top value=20kΩ (schematic designator R127)
R23 "RR0816P-272-D" FP-RR0816-IPC_C 4165,5270 r180 top value=2.7kΩ (schematic designator R135)
R24 "RMCF0603FT20K0" FP-AC0603-IPC_B 3560,5270 r0 top value=20kΩ (schematic designator R137)
R25 "ERA-3ARW102V" R0603_MD 4030,5270 r180 top value=1kΩ (schematic designator R136)
R26 "RC0603FR-07120RL" FP-AC0603-IPC_B 4165,5210 r0 top value=120Ω (schematic designator R133)
R27 "RR0816P-272-D" FP-RR0816-IPC_C 4165,5150 r180 top value=2.7kΩ (schematic designator R130)
R28 "RR0816P-273-D" FP-AC0603-IPC_B 3560,5150 r0 top value=27kΩ (schematic designator R129)
R29 "ERA-3ARW102V" R0603_MD 4165,5090 r0 top value=1kΩ (schematic designator R131)
R30 "RG1608P-103-BT5" FP-AC0603-IPC_B 3560,5030 r0 top value=10kΩ (schematic designator R128)
R31 "ERJ-3EKF49R9V" FP-MCR03-IPC_B 2890,4655 r180 top value=49.9Ω (schematic designator R51)
R32 "ERJ-3EKF49R9V" FP-MCR03-IPC_B 2890,4585 r180 top value=49.9Ω (schematic designator R93)
R33 "RR0816P-273-D" FP-AC0603-IPC_B 3560,4590 r0 top value=27kΩ (schematic designator R123)
R34 "RMCF0603FT20K0" FP-AC0603-IPC_B 3560,4530 r180 top value=20kΩ (schematic designator R116)
R35 "ERJ-3EKF49R9V" FP-MCR03-IPC_B 2890,4515 r180 top value=49.9Ω (schematic designator R12)
R36 "RR0816P-272-D" FP-RR0816-IPC_C 4165,4470 r180 top value=2.7kΩ (schematic designator R124)
R37 "RMCF0603FT20K0" FP-AC0603-IPC_B 3560,4470 r0 top value=20kΩ (schematic designator R126)
R38 "ERA-3ARW102V" R0603_MD 4030,4470 r180 top value=1kΩ (schematic designator R125)
R39 "ERJ-3EKF49R9V" FP-MCR03-IPC_B 2890,4445 r180 top value=49.9Ω (schematic designator R94)
R40 "RC0603FR-07120RL" FP-AC0603-IPC_B 4165,4410 r0 top value=120Ω (schematic designator R122)
R41 "RR0816P-272-D" FP-RR0816-IPC_C 4165,4350 r180 top value=2.7kΩ (schematic designator R119)
R42 "RR0816P-273-D" FP-AC0603-IPC_B 3560,4350 r0 top value=27kΩ (schematic designator R118)
R43 "ERA-3ARW102V" R0603_MD 4165,4290 r0 top value=1kΩ (schematic designator R120)
R44 "RG1608P-103-BT5" FP-AC0603-IPC_B 3560,4230 r0 top value=10kΩ (schematic designator R117)
R45 "RR0816P-273-D" FP-AC0603-IPC_B 3565,3800 r0 top value=27kΩ (schematic designator R112)
R46 "RMCF0603FT20K0" FP-AC0603-IPC_B 3565,3730 r180 top value=20kΩ (schematic designator R73)
R47 "RC1206FR-07249RL" FP-MCR18-IPC_A 1100,3665 r180 top value=249Ω (schematic designator R62)
R48 "RR0816P-272-D" FP-RR0816-IPC_C 4165,3670 r180 top value=2.7kΩ (schematic designator R113)
R49 "RMCF0603FT20K0" FP-AC0603-IPC_B 3565,3670 r0 top value=20k (schematic designator R115)
R50 "ERA-3ARW102V" R0603_MD 4030,3670 r180 top value=1kΩ (schematic designator R114)
R51 "RC0603FR-07120RL" FP-AC0603-IPC_B 4165,3610 r0 top value=120Ω (schematic designator R74)
R52 "RC0805FR-07499RL" FP-MCR10-IPC_A 1100,3565 r0 top value=499Ω (schematic designator R65)
R53 "RR0816P-272-D" FP-RR0816-IPC_C 4165,3550 r180 top value=2.7kΩ (schematic designator R109)
R54 "RR0816P-273-D" FP-AC0603-IPC_B 3565,3550 r0 top value=27kΩ (schematic designator R71)
R55 "ERA-3ARW102V" R0603_MD 4165,3490 r0 top value=1kΩ (schematic designator R110)
R56 "ERJ-6ENF2431V" FP-MCR10-IPC_A 1100,3465 r0 top value=2.43kΩ (schematic designator R138)
R57 "RG1608P-103-BT5" FP-AC0603-IPC_B 3565,3430 r0 top value=10kΩ (schematic designator R72)
R58 "RC0603FR-074K99L" FP-MCR03-IPC_B 3240,2965 r180 top value=4.99kΩ (schematic designator R50)
R59 "ERJ-PB3B3741V" FP-MCR03-IPC_B 3240,2845 r180 top value=3.74kΩ (schematic designator R1)
R60 "ERJ-PB3B3741V" FP-MCR03-IPC_B 3240,2725 r180 top value=3.74kΩ (schematic designator R59)
R61 "RC0603FR-074K99L" FP-MCR03-IPC_B 3240,2665 r0 top value=4.99kΩ (schematic designator R58)
R62 "RC0603FR-074K99L" FP-MCR03-IPC_B 3240,2365 r180 top value=4.99kΩ (schematic designator R85)
R63 "ERJ-PB3B1801V" FP-MCR03-IPC_B 3240,2245 r0 top value=1.8kΩ (schematic designator R75)
R64 "ERJ-PB3B1801V" FP-MCR03-IPC_B 3240,2125 r0 top value=1.8kΩ (schematic designator R77)
R65 "RC0603FR-074K99L" FP-MCR03-IPC_B 3240,2065 r0 top value=4.99kΩ (schematic designator R101)
R66 "RC0603FR-074K99L" FP-MCR03-IPC_B 3240,1680 r180 top value=4.99kΩ (schematic designator R11)
R67 "ERJ-PB3B3741V" FP-MCR03-IPC_B 3240,1560 r180 top value=3.74kΩ (schematic designator R4)
R68 "ERJ-PB3B3741V" FP-MCR03-IPC_B 3240,1440 r180 top value=3.74kΩ (schematic designator R20)
R69 "RC0603FR-074K99L" FP-MCR03-IPC_B 3240,1380 r0 top value=4.99kΩ (schematic designator R19)
R70 "RC0603FR-074K99L" FP-MCR03-IPC_B 3240,1080 r180 top value=4.99kΩ (schematic designator R92)
R71 "ERJ-PB3B1801V" FP-MCR03-IPC_B 3240,960 r0 top value=1.8kΩ (schematic designator R76)
R72 "RC0603JR-072M7L" FP-MCR03-IPC_B 580,890 r180 top value=2.7MΩ (schematic designator R66)
R73 "RC0603JR-072M7L" FP-MCR03-IPC_B 980,890 r180 top value=2.7MΩ (schematic designator R67)
R74 "ERJ-PB3B1801V" FP-MCR03-IPC_B 3240,840 r0 top value=1.8kΩ (schematic designator R78)
R75 "RC0603FR-07100KL" FP-MCR03-IPC_B 580,830 r180 top value=100kΩ (schematic designator R68)
R76 "RC0603FR-074K99L" FP-MCR03-IPC_B 3240,780 r0 top value=4.99kΩ (schematic designator R108)
R77 "RC2512JK-070RL" FP-RC2512-0_65-IPC_C 225,675 r270 top value=0Ω (schematic designator R63)
R78 "RC2512JK-070RL" FP-RC2512-0_65-IPC_C 365,675 r270 top value=0Ω (schematic designator R60)
R79 "ERJ-3EKF2202V" FP-MCR03-IPC_B 580,770 r0 top value=22kΩ (schematic designator R64)
R80 "ERJ-3EKF2003V" FP-MCR03-IPC_B 980,770 r180 top value=200kΩ (schematic designator R70)
R81 "RC0603FR-07100KL" FP-MCR03-IPC_B 980,710 r0 top value=100kΩ (schematic designator R69)
R82 "RC0603JR-07120RL" FP-MCR03-IPC_B 1520,580 r0 top value=120Ω (schematic designator R3)
R83 "RC0603FR-07120RL" FP-AC0603-IPC_B 3230,5955 r90 bottom value=120Ω (schematic designator R26)
R84 "RC0603FR-07120RL" FP-AC0603-IPC_B 3170,5955 r90 bottom value=120Ω (schematic designator R27)
R85 "RC0603FR-07120RL" FP-AC0603-IPC_B 3110,5955 r90 bottom value=120Ω (schematic designator R28)
R86 "RC0603FR-07120RL" FP-AC0603-IPC_B 3050,5955 r90 bottom value=120Ω (schematic designator R29)
R87 "CRCW06030000Z0EB" FP-MCR03-IPC_B 2500,5740 r0 bottom value=0Ω (schematic designator R147)
R88 "CRCW06030000Z0EB" FP-MCR03-IPC_B 2500,5600 r0 bottom value=0Ω (schematic designator R146)
R89 "CRCW06030000Z0EB" FP-MCR03-IPC_B 2500,5460 r0 bottom value=0Ω (schematic designator R145)
R90 "CRCW06030000Z0EB" FP-MCR03-IPC_B 2500,5320 r0 bottom value=0Ω (schematic designator R144)
R91 "CRCW06030000Z0EB" FP-MCR03-IPC_B 2500,4900 r0 bottom value=0Ω (schematic designator R143)
R92 "CRCW06030000Z0EB" FP-MCR03-IPC_B 2500,4760 r0 bottom value=0Ω (schematic designator R142)
R93 "ERJ-3EKF49R9V" FP-MCR03-IPC_B 2500,4620 r0 bottom value=49.9Ω (schematic designator R132)
R94 "ERJ-3EKF49R9V" FP-MCR03-IPC_B 2500,4480 r0 bottom value=49.9Ω (schematic designator R121)
R95 "ERJ-3EKF49R9V" FP-MCR03-IPC_B 2500,4340 r0 bottom value=49.9Ω (schematic designator R111)
R96 "RC0603FR-07680RL" FP-MCR03-IPC_B 1635,3665 r180 bottom value=680Ω (schematic designator R141)
R97 "RC0603FR-07680RL" FP-MCR03-IPC_B 1636.38,3565 r180 bottom value=680Ω (schematic designator R140)
R98 "RC0603FR-07680RL" FP-MCR03-IPC_B 1631.38,3465 r180 bottom value=680Ω (schematic designator R139)
R99 "TNPW1206249KBEEA" RESC3216X65X50NL15T25 4420,2965 r180 bottom value=249kΩ (schematic designator R2)
R100 "TNPW1206249KBEEA" RESC3216X65X50NL15T25 4220,2965 r180 bottom value=249kΩ (schematic designator R45)
R101 "TNPW1206249KBEEA" RESC3216X65X50NL15T25 4020,2965 r180 bottom value=249kΩ (schematic designator R46)
R102 "TNPW1206249KBEEA" RESC3216X65X50NL15T25 3820,2965 r180 bottom value=249kΩ (schematic designator R47)
R103 "TNPW1206249KBEEA" RESC3216X65X50NL15T25 3620,2965 r180 bottom value=249kΩ (schematic designator R48)
R104 "TNPW1206249KBEEA" RESC3216X65X50NL15T25 3420,2965 r180 bottom value=249kΩ (schematic designator R49)
R105 "TNPW1206249KBEEA" RESC3216X65X50NL15T25 4420,2665 r180 bottom value=249kΩ (schematic designator R52)
R106 "TNPW1206249KBEEA" RESC3216X65X50NL15T25 4220,2665 r180 bottom value=249kΩ (schematic designator R53)
R107 "TNPW1206249KBEEA" RESC3216X65X50NL15T25 4020,2665 r180 bottom value=249kΩ (schematic designator R54)
R108 "TNPW1206249KBEEA" RESC3216X65X50NL15T25 3820,2665 r180 bottom value=249kΩ (schematic designator R55)
R109 "TNPW1206249KBEEA" RESC3216X65X50NL15T25 3620,2665 r180 bottom value=249kΩ (schematic designator R56)
R110 "TNPW1206249KBEEA" RESC3216X65X50NL15T25 3420,2665 r180 bottom value=249kΩ (schematic designator R57)
R111 "TNPW1206249KBEEA" RESC3216X65X50NL15T25 4420,2365 r180 bottom value=249kΩ (schematic designator R79)
R112 "TNPW1206249KBEEA" RESC3216X65X50NL15T25 4220,2365 r180 bottom value=249kΩ (schematic designator R80)
R113 "TNPW1206249KBEEA" RESC3216X65X50NL15T25 4020,2365 r180 bottom value=249kΩ (schematic designator R81)
R114 "TNPW1206249KBEEA" RESC3216X65X50NL15T25 3820,2365 r180 bottom value=249kΩ (schematic designator R82)
R115 "TNPW1206249KBEEA" RESC3216X65X50NL15T25 3620,2365 r180 bottom value=249kΩ (schematic designator R83)
R116 "TNPW1206249KBEEA" RESC3216X65X50NL15T25 3420,2365 r180 bottom value=249kΩ (schematic designator R84)
R117 "TNPW1206249KBEEA" RESC3216X65X50NL15T25 4420,2065 r180 bottom value=249kΩ (schematic designator R95)
R118 "TNPW1206249KBEEA" RESC3216X65X50NL15T25 4220,2065 r180 bottom value=249kΩ (schematic designator R96)
R119 "TNPW1206249KBEEA" RESC3216X65X50NL15T25 4020,2065 r180 bottom value=249kΩ (schematic designator R97)
R120 "TNPW1206249KBEEA" RESC3216X65X50NL15T25 3820,2065 r180 bottom value=249kΩ (schematic designator R98)
R121 "TNPW1206249KBEEA" RESC3216X65X50NL15T25 3620,2065 r180 bottom value=249kΩ (schematic designator R99)
R122 "TNPW1206249KBEEA" RESC3216X65X50NL15T25 3420,2065 r180 bottom value=249kΩ (schematic designator R100)
R123 "TNPW1206249KBEEA" RESC3216X65X50NL15T25 4420,1680 r180 bottom value=249kΩ (schematic designator R5)
R124 "TNPW1206249KBEEA" RESC3216X65X50NL15T25 4220,1680 r180 bottom value=249kΩ (schematic designator R6)
R125 "TNPW1206249KBEEA" RESC3216X65X50NL15T25 4020,1680 r180 bottom value=249kΩ (schematic designator R7)
R126 "TNPW1206249KBEEA" RESC3216X65X50NL15T25 3820,1680 r180 bottom value=249kΩ (schematic designator R8)
R127 "TNPW1206249KBEEA" RESC3216X65X50NL15T25 3620,1680 r180 bottom value=249kΩ (schematic designator R9)
R128 "TNPW1206249KBEEA" RESC3216X65X50NL15T25 3420,1680 r180 bottom value=249kΩ (schematic designator R10)
R129 "TNPW1206249KBEEA" RESC3216X65X50NL15T25 4420,1380 r180 bottom value=249kΩ (schematic designator R13)
R130 "TNPW1206249KBEEA" RESC3216X65X50NL15T25 4220,1380 r180 bottom value=249kΩ (schematic designator R14)
R131 "TNPW1206249KBEEA" RESC3216X65X50NL15T25 4020,1380 r180 bottom value=249kΩ (schematic designator R15)
R132 "TNPW1206249KBEEA" RESC3216X65X50NL15T25 3820,1380 r180 bottom value=249kΩ (schematic designator R16)
R133 "TNPW1206249KBEEA" RESC3216X65X50NL15T25 3620,1380 r180 bottom value=249kΩ (schematic designator R17)
R134 "TNPW1206249KBEEA" RESC3216X65X50NL15T25 3420,1380 r180 bottom value=249kΩ (schematic designator R18)
R135 "TNPW1206249KBEEA" RESC3216X65X50NL15T25 4420,1080 r180 bottom value=249kΩ (schematic designator R86)
R136 "TNPW1206249KBEEA" RESC3216X65X50NL15T25 4220,1080 r180 bottom value=249kΩ (schematic designator R87)
R137 "TNPW1206249KBEEA" RESC3216X65X50NL15T25 4020,1080 r180 bottom value=249kΩ (schematic designator R88)
R138 "TNPW1206249KBEEA" RESC3216X65X50NL15T25 3820,1080 r180 bottom value=249kΩ (schematic designator R89)
R139 "TNPW1206249KBEEA" RESC3216X65X50NL15T25 3620,1080 r180 bottom value=249kΩ (schematic designator R90)
R140 "TNPW1206249KBEEA" RESC3216X65X50NL15T25 3420,1080 r180 bottom value=249kΩ (schematic designator R91)
R141 "PE2512FKE7W0R01L" FP-RL2512-IPC_A 790,915 r180 bottom value=10mΩ (schematic designator R61)
R142 "TNPW1206249KBEEA" RESC3216X65X50NL15T25 4420,780 r180 bottom value=249kΩ (schematic designator R102)
R143 "TNPW1206249KBEEA" RESC3216X65X50NL15T25 4220,780 r180 bottom value=249kΩ (schematic designator R103)
R144 "TNPW1206249KBEEA" RESC3216X65X50NL15T25 4020,780 r180 bottom value=249kΩ (schematic designator R104)
R145 "TNPW1206249KBEEA" RESC3216X65X50NL15T25 3820,780 r180 bottom value=249kΩ (schematic designator R105)
R146 "TNPW1206249KBEEA" RESC3216X65X50NL15T25 3620,780 r180 bottom value=249kΩ (schematic designator R106)
R147 "TNPW1206249KBEEA" RESC3216X65X50NL15T25 3420,780 r180 bottom value=249kΩ (schematic designator R107)
TP1 "5011" KSTN-5011_V 4140,8400 r0 top value=BLACK (schematic designator TP8)
TP2 "5011" KSTN-5011_V 4305,8400 r0 top value=BLACK (schematic designator TP4)
TP3 "5010" KSTN-5010_V 825,3030 r0 top value=RED
TP4 "5010" KSTN-5010_V 1175,3030 r0 top value=RED (schematic designator TP2)
TP5 "5010" KSTN-5010_V 1525,3030 r0 top value=RED (schematic designator TP1)
TP6 "5011" KSTN-5011_V 825,2730 r0 top value=BLACK
TP7 "5011" KSTN-5011_V 1175,2730 r0 top value=BLACK (schematic designator TP5)
TP8 "5011" KSTN-5011_V 1525,2730 r0 top value=BLACK (schematic designator TP7)
U1 "TMDSCNCD28379D" TMDSCNCD28379D 2700,5350 r270 top locked value=N/A (schematic designator U13)
U2 "AM26LV32EIPWR" PW0016A_M 3140,8140 r0 top value=N/A (schematic designator U7)
U3 "SN74LV541ATPWR" PW0020A_L 3140,7640 r0 top value=N/A
U4 "AM26LV32EIPWR" PW0016A_M 3140,7140 r0 top value=N/A
U5 "SN74LV541ATPWR" PW0020A_L 3140,6640 r0 top value=N/A (schematic designator U8)
U6 "AM26LV31EIPWR" PW0016A_M 3140,6140 r180 top value=N/A
U7 "AM26LV31EIPWR" PW0016A_M 3140,5640 r180 top value=N/A (schematic designator U5)
U8 "AD8618ARUZ-REEL" ADI-RU-14_L 3795,5165 r180 top value=N/A (schematic designator U18)
U9 "REF2030AIDDCT" FP-DDC0005A-MFG 3692.6,4810 r90 top value=N/A (schematic designator U21)
U10 "AD8618ARUZ-REEL" ADI-RU-14_L 3795,4365 r180 top value=N/A (schematic designator U17)
U11 "AD8618ARUZ-REEL" ADI-RU-14_L 3795,3565 r180 top value=N/A (schematic designator U14)
U12 "AD8615AUJZ-REEL7" ADI-UJ-5_M 3065,2815 r90 top value=N/A (schematic designator U9)
U13 "R-78E3.3-1.0" CONV_R-78E3.3-1.0 590,2250 r90 top value=N/A (schematic designator U12)
U14 "R-78E5.0-1.0" CONV_R-78E5.0-1.0 1280,2250 r90 top value=N/A (schematic designator U11)
U15 "AD8615AUJZ-REEL7" ADI-UJ-5_M 3065,2215 r90 top value=N/A
U16 "REF2030AIDDCT" FP-DDC0005A-MFG 3065,1875 r270 top value=N/A (schematic designator U20)
U17 "AD8615AUJZ-REEL7" ADI-UJ-5_M 3065,1530 r90 top value=N/A (schematic designator U2)
U18 "R1SE-3.305/H2-R" FP-R1SE-0505-R-MFG 2110,920 r0 top value=N/A (schematic designator U19)
U19 "ISO1050DUBR" DUB0008A_M 1525,865 r270 top value=N/A (schematic designator U1)
U20 "AD8615AUJZ-REEL7" ADI-UJ-5_M 3065,930 r90 top value=N/A (schematic designator U16)
U21 "LTC4368IMS-2#PBF" SOP50P490X110-10N 780,800 r180 top value=N/A (schematic designator U10)

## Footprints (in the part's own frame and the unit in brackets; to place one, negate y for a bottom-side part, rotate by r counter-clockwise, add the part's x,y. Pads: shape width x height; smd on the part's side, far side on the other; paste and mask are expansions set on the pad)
2-406541-2 [mm] "CONN MOD JACK R/A 8P8C SHLD"
  round 1.398 hole 0.89: 1(3.58,2.54) 2(2.56,4.32) 3(1.54,2.54) 4(0.52,4.32) 5(-0.5,2.54) 6(-1.52,4.32) 7(-2.54,2.54) 8(-3.56,4.32)
  round 2.087 hole 1.57: 9(8.13,3.43) 10(-8.13,3.43)
  round 0 hole 3.25 unplated: 11(-6.35,0) 11(6.35,0)
  silkscreen extent -9.5,-5 9.5,10.47, body extent -8.13,-5.28 8.13,10.47, height 13.4
1728879 [mm] "TERM BLOCK HDR 4POS 90DEG 7.62MM"
  round 2.4 hole 1.4: 1(-11.43,0) 2(-3.81,0) 3(3.81,0) 4(11.43,0)
  silkscreen extent -15.24,-10 15.24,2, body extent -15.24,-10 15.19,2, height 8.57
ADI-RU-14_L [mm] "SOP, 14-Leads, Body 5x4.4mm, Pitch 0.65mm, IPC High Density"
  oval 1.25x0.35 smd: 1(-2.825,1.95) 2(-2.825,1.3) 3(-2.825,0.65) 4(-2.825,0) 5(-2.825,-0.65) 6(-2.825,-1.3) 7(-2.825,-1.95) 8(2.825,-1.95) 9(2.825,-1.3) 10(2.825,-0.65) 11(2.825,0) 12(2.825,0.65) 13(2.825,1.3) 14(2.825,1.95)
  silkscreen extent -2.95,-2.55 1.8,2.8, body extent -2.25,-2.55 2.25,2.55, height 1.2
ADI-UJ-5_M [mm] "SOT23, 5-Leads, Body 2.9x1.6mm, Pitch 0.95mm, IPC Low Density"
  rect 1.15x0.7 smd: 1(-1.225,0.95) 2(-1.225,0) 3(-1.225,-0.95) 4(1.225,-0.95) 5(1.225,0.95)
  silkscreen extent -1.35,-1.45 0.25,1.97, body extent -0.8,-1.45 0.8,1.45, height 1
CONV_R-78E3.3-1.0 [mm]
  rect 1.508x1.508 hole 1: 1(-2.54,-2.25)
  round 1.508 hole 1: 2(0,-2.25) 3(2.54,-2.25)
  silkscreen extent -6.5,-4.25 5.75,4.25, body extent -5.8,-4.25 5.8,4.25, height 9.9
CONV_R-78E5.0-1.0 [mm]
  rect 1.508x1.508 hole 1: 1(-2.54,-2.25)
  round 1.508 hole 1: 2(0,-2.25) 3(2.54,-2.25)
  silkscreen extent -6.5,-4.25 5.75,4.25, body extent -5.8,-4.25 5.8,4.25, height 9.9
CUI-PJ-102B_V [mm] "THD, 3-Leads, Body 14.4x9mm, Height 11mm"
  rect 1.5x2.1 hole 1 slot 1.6 at 90 deg: 1(-3,0) 2(3,0)
  rect 2.1x1.5 hole 1 slot 1.6 at 0 deg: 3(0,4.7)
  silkscreen extent -4.42,-4.5 10.7,4.9, body extent -3.7,-4.5 10.7,4.9, height 11
DUB0008A_M [mm] "SOP, 8-Leads, Body 6.7x9.6mm, Pitch 2.54mm, IPC Low Density"
  rrect14% 2.55x0.7 smd: 1(-4.625,3.81) 2(-4.625,1.27) 3(-4.625,-1.27) 4(-4.625,-3.81) 5(4.625,-3.81) 6(4.625,-1.27) 7(4.625,1.27) 8(4.625,3.81)
  silkscreen extent -4.75,-4.8 2.95,4.84, body extent -5.24,-4.75 5.24,4.75, height 4.85
FP-61301221121-MFG [mm]
  rect 1.7x1.7 hole 1.1 paste-1000 mask+0: 1(-6.35,-1.27)
  round 1.7 hole 1.1 paste-1000 mask+0: 2(-6.35,1.27) 3(-3.81,-1.27) 4(-3.81,1.27) 5(-1.27,-1.27) 6(-1.27,1.27) 7(1.27,-1.27) 8(1.27,1.27) 9(3.81,-1.27) 10(3.81,1.27) 11(6.35,-1.27) 12(6.35,1.27)
  silkscreen extent -8.38,-2.62 7.77,2.62, body extent -7.87,-2.72 7.87,2.72, height 0.25
FP-AC0603-IPC_B [mil]
  rect 33.81x35.91 smd paste+0 mask+0: 1(-30.58,0) 2(30.58,0)
  silkscreen extent -6,-14 6,14, body extent -31,-18 31,18, height 20
FP-C0603C-CF-IPC_B [mil]
  rect 39.63x37.73 smd paste+0 mask+0: 1(-28.58,0) 2(28.58,0)
  silkscreen extent -48,-35 48,35, body extent -58,-29 58,29, height 10
FP-CBR06C-MFG [mm]
  rect 0.75x0.9 smd paste+0 mask+0: 1(-0.6,0) 2(0.6,0)
  silkscreen extent -0.85,-0.82 0.85,0.82, body extent -1.2,-0.6 1.2,0.6, height 0.25
FP-CL31-IPC_B [mil]
  rect 51.4x69.22 smd paste+0 mask+0: 1(-54.19,0) 2(54.19,0)
  silkscreen extent -17,-35 17,35, body extent -63,-31 63,31, height 55
FP-DDC0005A-MFG [mm]
  rect 1.1x0.6 smd paste+0 mask+0: 1(-1.35,0.95) 2(-1.35,0) 3(-1.35,-0.95) 4(1.35,-0.95) 5(1.35,0.95)
  silkscreen extent -2.6,-1.53 0.87,1.53, body extent -2,-1.63 2,1.63, height 0.25
FP-GCM188-0_1-IPC_A [mil]
  rect 45.62x39.85 smd paste+0 mask+0: 1(-32.55,0) 2(32.55,0)
  silkscreen extent -55,-36 55,36, body extent -31,-16 31,16, height 35
FP-LTST-C171GKT-MFG [mm]
  rect 1.2x1.2 smd paste+0 mask+0: 1(-1.05,0) 2(1.05,0)
  silkscreen extent -2.37,-1.05 1.05,1.05, body extent -1.75,-0.77 1.75,0.77, height 0.25
FP-LTST-C171GKT-MFG-RED [mm]
  rect 1.2x1.2 smd paste+0 mask+0: 1(-1.05,0) 2(1.05,0)
  silkscreen extent -2.37,-1.05 1.05,1.05, body extent -1,-0.63 1,0.63, height 0.8
FP-LTST-C171GKT-MFG-YELLOW [mm]
  rect 1.2x1.2 smd paste+0 mask+0: 1(-1.05,0) 2(1.05,0)
  silkscreen extent -2.37,-1.05 1.05,1.05, body extent -1,-0.63 1,0.63, height 0.8
FP-MCR03-IPC_B [mil]
  rect 37.72x35.91 smd paste+0 mask+0: 1(-28.62,0) 2(28.62,0)
  silkscreen extent -47,-34 47,34, body extent -31,-16 31,16, height 22
FP-MCR10-IPC_A [mil]
  rect 49.53x57.56 smd paste+0 mask+0: 1(-38.46,0) 2(38.46,0)
  silkscreen extent -63,-45 63,45, body extent -83,-48 83,48, height 10
FP-MCR18-IPC_A [mil]
  rect 57.31x73.16 smd paste+0 mask+0: 1(-59.1,0) 2(59.1,0)
  silkscreen extent -19,-37 19,37, body extent -107,-56 107,56, height 10
FP-MLZ2012-0_85-IPC_B [mil]
  rect 53.32x57.33 smd paste+0 mask+0: 1(-30.55,0) 2(30.55,0)
  silkscreen extent -57,-44 57,44, body extent -67,-39 67,39, height 10
FP-PowerDI5060-8-MFG [mm]
  rect 0.61x1.27 smd paste+0 mask+0: 1(-1.905,-2.67) 2(-0.635,-2.67) 3(0.635,-2.67) 4(1.905,-2.67)
  rect 3x2 smd paste+0 mask+0: 5(0,1.05)
  Top Layer region: 2.05,-1.215 -2.05,-1.215 -2.05,-1.035 -2.805,-1.035 -2.805,-0.435 -2.05,-0.435 -2.05,1.39 -2.805,1.39 -2.805,1.99 -2.05,1.99 -2.05,2.285 -2.21,2.285 -2.21,3.305 -1.6,3.305 -1.6,2.595 -0.94,2.595 -0.94,3.305 -0.33,3.305 -0.33,2.595 0.33,2.595 0.33,3.305 0.94,3.305 0.94,2.595 1.6,2.595 1.6,3.305 2.21,3.305 2.21,2.285 2.05,2.285 2.05,1.99 2.805,1.99 2.805,1.39 2.05,1.39 2.05,-0.435 2.805,-0.435 2.805,-1.035 2.05,-1.035
  silkscreen extent -3.2,-2.74 2.55,-1.59, body extent -2.57,-3.08 2.57,3.08, height 1.15
FP-R1SE-0505-R-MFG [mm]
  rect 1.8x1.2 smd paste+0 mask+0: 1(-5.1,3.81) 2(-5.1,1.27) 4(-5.1,-3.81) 5(5.1,-3.81) 8(5.1,3.81)
  silkscreen extent -6.77,-6.5 5.35,6.5, body extent -6.1,-6.6 6.1,6.6, height 0.25
FP-RC2512-0_65-IPC_C [mil]
  rect 37.72x124.34 smd paste+0 mask+0: 1(-114.25,0) 2(114.25,0)
  silkscreen extent -84,-64 84,64, body extent -137,-68 137,68, height 10
FP-RL2512-IPC_A [mil]
  rect 53.47x136.15 smd paste+0 mask+0: 1(-122.13,0) 2(122.13,0)
  silkscreen extent -84,-68 84,68, body extent -123,-63 127,63, height 26
FP-RR0816-IPC_C [mil]
  rect 33.66x35.68 smd paste+0 mask+0: 1(-24.63,0) 2(24.63,0)
  silkscreen extent -41,-35 41,35, body extent -45,-24 45,24, height 10
FP-SBH11-PBPC-D08-ST-BK-MFG [mm]
  rect 1.55x1.55 hole 1 paste-1000 mask+0: 1(-8.89,-1.42)
  round 1.55 hole 1 paste-1000 mask+0: 2(-8.89,1.12) 3(-6.35,-1.42) 4(-6.35,1.12) 5(-3.81,-1.42) 6(-3.81,1.12) 7(-1.27,-1.42) 8(-1.27,1.12) 9(1.27,-1.42) 10(1.27,1.12) 11(3.81,-1.42) 12(3.81,1.12) 13(6.35,-1.42) 14(6.35,1.12) 15(8.89,-1.42) 16(8.89,1.12)
  silkscreen extent -14.01,-5.29 14.01,4.65, body extent -14.11,-4.75 14.11,4.75, height 0.25
KSTN-5010_V [mm] "Test Point, Dia 3.17mm"
  round 2.1 hole 1.6: 1(0,0)
  silkscreen extent -1.59,-1.58 1.59,1.58, body extent -1.59,-1.59 1.59,1.59, height 8.13
KSTN-5011_V [mm] "Test Point, Dia 3.17mm"
  round 2.1 hole 1.6: 1(0,0)
  silkscreen extent -1.59,-1.58 1.59,1.58, body extent -1.59,-1.59 1.59,1.59, height 8.13
L717SDE09PA4CH4RC309 [mm] "CONN D-SUB PLUG 9POS R/A SLDR"
  round 1.508 hole 1: 1(-5.54,1.42) 2(-2.77,1.42) 3(0,1.42) 4(2.77,1.42) 5(5.54,1.42) 6(-4.155,-1.42) 7(-1.385,-1.42) 8(1.385,-1.42) 9(4.155,-1.42)
  round 4.066 hole 3.05: 10(-12.495,0) 11(12.495,0)
  silkscreen extent -15.7,-8.5 15.7,3.4, body extent -15.4,-15.6 15.41,3, height 12.55
MH_M4_P [mm] "M4 plated mounting hole"
  round 10 hole 4.5: 1(0,0)
PW0016A_M [mm] "SOP, 16-Leads, Body 5.1x4.5mm, Pitch 0.65mm, IPC Low Density"
  rrect22% 1.6x0.45 smd: 1(-3.05,2.275) 2(-3.05,1.625) 3(-3.05,0.975) 4(-3.05,0.325) 5(-3.05,-0.325) 6(-3.05,-0.975) 7(-3.05,-1.625) 8(-3.05,-2.275) 9(3.05,-2.275) 10(3.05,-1.625) 11(3.05,-0.975) 12(3.05,-0.325) 13(3.05,0.325) 14(3.05,0.975) 15(3.05,1.625) 16(3.05,2.275)
  silkscreen extent -3.17,-2.55 1.85,3.17, body extent -3.21,-2.5 3.21,2.5, height 1
PW0020A_L [mm] "SOP, 20-Leads, Body 6.6x4.5mm, Pitch 0.65mm, IPC High Density"
  rrect25% 1.2x0.4 smd: 1(-2.85,2.925) 2(-2.85,2.275) 3(-2.85,1.625) 4(-2.85,0.975) 5(-2.85,0.325) 6(-2.85,-0.325) 7(-2.85,-0.975) 8(-2.85,-1.625) 9(-2.85,-2.275) 10(-2.85,-2.925) 11(2.85,-2.925) 12(2.85,-2.275) 13(2.85,-1.625) 14(2.85,-0.975) 15(2.85,-0.325) 16(2.85,0.325) 17(2.85,0.975) 18(2.85,1.625) 19(2.85,2.275) 20(2.85,2.925)
  silkscreen extent -2.97,-3.3 1.85,3.8, body extent -3.21,-3.25 3.21,3.25, height 1
R0603_MD [mm] "Chip Resistor, 0603, IPC Medium Density"
  rect 0.55x0.9 smd: 1(-0.775,0) 2(0.775,0)
  silkscreen extent -0.1,-0.35 0.1,0.35, body extent -0.76,-0.46 0.76,0.46, height 0.5
RESC3216X65X50NL15T25 [mm] "Chip Resistor, 2-Leads, Body 3.20x1.60mm, IPC Medium Density"
  rect 1.25x1.75 smd: 1(-1.4,0) 2(1.4,0)
  silkscreen extent -0.4,-0.77 0.4,0.77, body extent -1.68,-0.87 1.68,0.87, height 0.65
SOP50P490X110-10N [mm]
  rect 1.425x0.3 smd: 1(-2.212,1) 2(-2.212,0.5) 3(-2.212,0) 4(-2.212,-0.5) 5(-2.212,-1) 6(2.212,-1) 7(2.212,-0.5) 8(2.212,0) 9(2.212,0.5) 10(2.212,1)
  silkscreen extent -2.92,-1.5 1.15,1.5, body extent -2.45,-1.5 2.45,1.5, height 1.1
TMDSCNCD28379D [mm]
  rect 0.5x1.65 smd: 1(25.2,0.925) 3(24.4,0.925) 5(23.6,0.925) 7(22.8,0.925) 9(22,0.925) 11(21.2,0.925) 13(20.4,0.925) 15(19.6,0.925) 17(18.8,0.925) 19(18,0.925) 21(17.2,0.925) 23(16.4,0.925) 25(15.6,0.925) 27(14.8,0.925) 29(14,0.925) 31(13.2,0.925) 33(12.4,0.925) 35(11.6,0.925) 37(10.8,0.925) 39(10,0.925) 41(9.2,0.925) 43(8.4,0.925) 45(7.6,0.925) 47(6.8,0.925) 49(6,0.925) 51(5.2,0.925) 53(4.4,0.925) 55(3.6,0.925) 57(-0.4,0.925) 59(-1.2,0.925) 61(-2,0.925) 63(-2.8,0.925) 65(-3.6,0.925) 67(-4.4,0.925) 69(-5.2,0.925) 71(-6,0.925) 73(-6.8,0.925) 75(-7.6,0.925) 77(-8.4,0.925) 79(-9.2,0.925) 81(-10,0.925) 83(-10.8,0.925) 85(-11.6,0.925) 87(-12.4,0.925) 89(-13.2,0.925) 91(-14,0.925) 93(-14.8,0.925) 95(-15.6,0.925) 97(-16.4,0.925) 99(-17.2,0.925) 101(-18,0.925) 103(-18.8,0.925) 105(-19.6,0.925) 107(-20.4,0.925) 109(-21.2,0.925) 111(-22,0.925) 113(-22.8,0.925) 115(-23.6,0.925) 117(-24.4,0.925) 119(-25.2,0.925) 121(-46.273,0.925) 123(-47.073,0.925) 125(-47.873,0.925) 127(-48.673,0.925) 129(-49.473,0.925) 131(-50.273,0.925) 133(-51.073,0.925) 135(-51.873,0.925) 137(-52.673,0.925) 139(-53.473,0.925) 141(-54.273,0.925) 143(-55.073,0.925) 145(-55.873,0.925) 147(-56.673,0.925) 149(-57.473,0.925) 151(-58.273,0.925) 153(-59.073,0.925) 155(-59.873,0.925) 157(-60.673,0.925) 159(-61.473,0.925) 161(-62.273,0.925) 163(-63.073,0.925) 165(-63.873,0.925) 167(-64.673,0.925) 169(-65.473,0.925) 171(-66.273,0.925) 173(-67.073,0.925) 175(-67.873,0.925) 177(-68.673,0.925) 179(-69.473,0.925)
  rect 0.5x1.35 smd: 2(25.2,-1.075) 4(24.4,-1.075) 6(23.6,-1.075) 8(22.8,-1.075) 10(22,-1.075) 12(21.2,-1.075) 14(20.4,-1.075) 16(19.6,-1.075) 18(18.8,-1.075) 20(18,-1.075) 22(17.2,-1.075) 24(16.4,-1.075) 26(15.6,-1.075) 28(14.8,-1.075) 30(14,-1.075) 32(13.2,-1.075) 34(12.4,-1.075) 36(11.6,-1.075) 38(10.8,-1.075) 40(10,-1.075) 42(9.2,-1.075) 44(8.4,-1.075) 46(7.6,-1.075) 48(6.8,-1.075) 50(6,-1.075) 52(5.2,-1.075) 54(4.4,-1.075) 56(3.6,-1.075) 58(-0.4,-1.075) 60(-1.2,-1.075) 62(-2,-1.075) 64(-2.8,-1.075) 66(-3.6,-1.075) 68(-4.4,-1.075) 70(-5.2,-1.075) 72(-6,-1.075) 74(-6.8,-1.075) 76(-7.6,-1.075) 78(-8.4,-1.075) 80(-9.2,-1.075) 82(-10,-1.075) 84(-10.8,-1.075) 86(-11.6,-1.075) 88(-12.4,-1.075) 90(-13.2,-1.075) 92(-14,-1.075) 94(-14.8,-1.075) 96(-15.6,-1.075) 98(-16.4,-1.075) 100(-17.2,-1.075) 102(-18,-1.075) 104(-18.8,-1.075) 106(-19.6,-1.075) 108(-20.4,-1.075) 110(-21.2,-1.075) 112(-22,-1.075) 114(-22.8,-1.075) 116(-23.6,-1.075) 118(-24.4,-1.075) 120(-25.2,-1.075) 122(-46.273,-1.075) 124(-47.073,-1.075) 126(-47.873,-1.075) 128(-48.673,-1.075) 130(-49.473,-1.075) 132(-50.273,-1.075) 134(-51.073,-1.075) 136(-51.873,-1.075) 138(-52.673,-1.075) 140(-53.473,-1.075) 142(-54.273,-1.075) 144(-55.073,-1.075) 146(-55.873,-1.075) 148(-56.673,-1.075) 150(-57.473,-1.075) 152(-58.273,-1.075) 154(-59.073,-1.075) 156(-59.873,-1.075) 158(-60.673,-1.075) 160(-61.473,-1.075) 162(-62.273,-1.075) 164(-63.073,-1.075) 166(-63.873,-1.075) 168(-64.673,-1.075) 170(-65.473,-1.075) 172(-66.273,-1.075) 174(-67.073,-1.075) 176(-67.873,-1.075) 178(-68.673,-1.075) 180(-69.473,-1.075)
  round 1.318 hole 0.81: MH1(27.35,-7) MH2(-27.35,-7) MH3(-44.123,-7) MH4(-71.623,-7)
  round 6 hole 2.489: MH5(1.341,-32.989) MH6(-65.962,-35.522) MH7(-43.118,-51.404)
  round 1.4 hole 1.4 unplated: ""(-72.573,0) ""(-43.173,0) ""(-28.3,0) ""(28.3,0)
  silkscreen extent -74.77,-9 29.9,2.75, body extent -74.17,-54.55 33.5,2.75, height 5.2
